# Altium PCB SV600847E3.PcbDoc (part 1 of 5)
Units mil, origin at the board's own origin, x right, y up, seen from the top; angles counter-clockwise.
Board outline 5404 x 2680 mil, 10 copper layers (Top Layer L1, Gnd-Plane - L2, Signals - L3, Gnd-Plane - L4, Pwr Plane - L5, Signals - L6, Gnd-Plane - L7, Signals - L8, Gnd-Plane - L9, Bottom Layer - L10), stack 57.8 mil thick; 517 components, 320 nets, 1784 pads, 1289 vias.
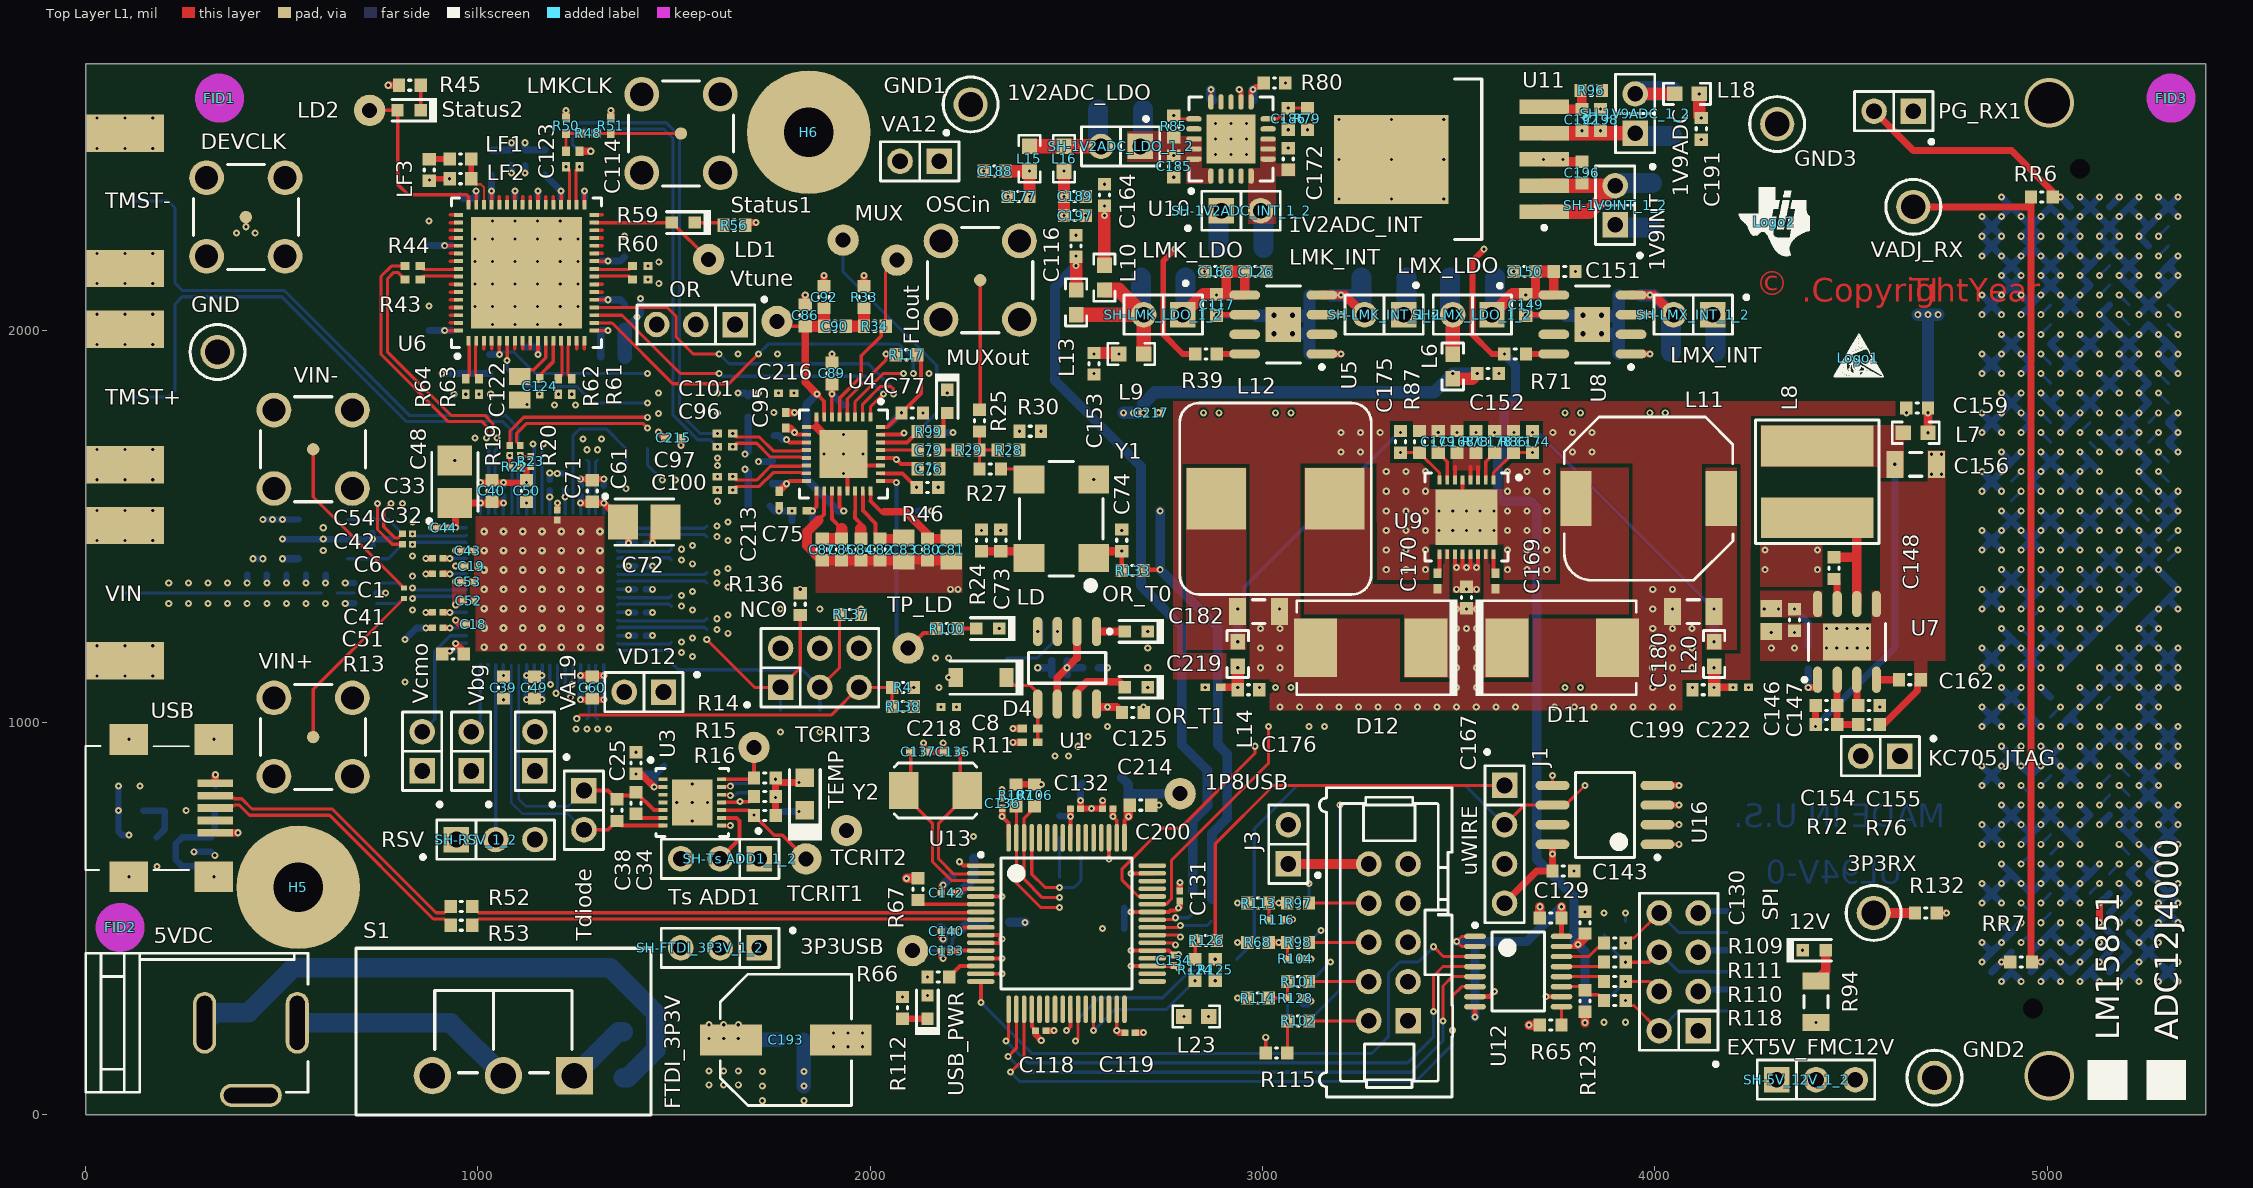
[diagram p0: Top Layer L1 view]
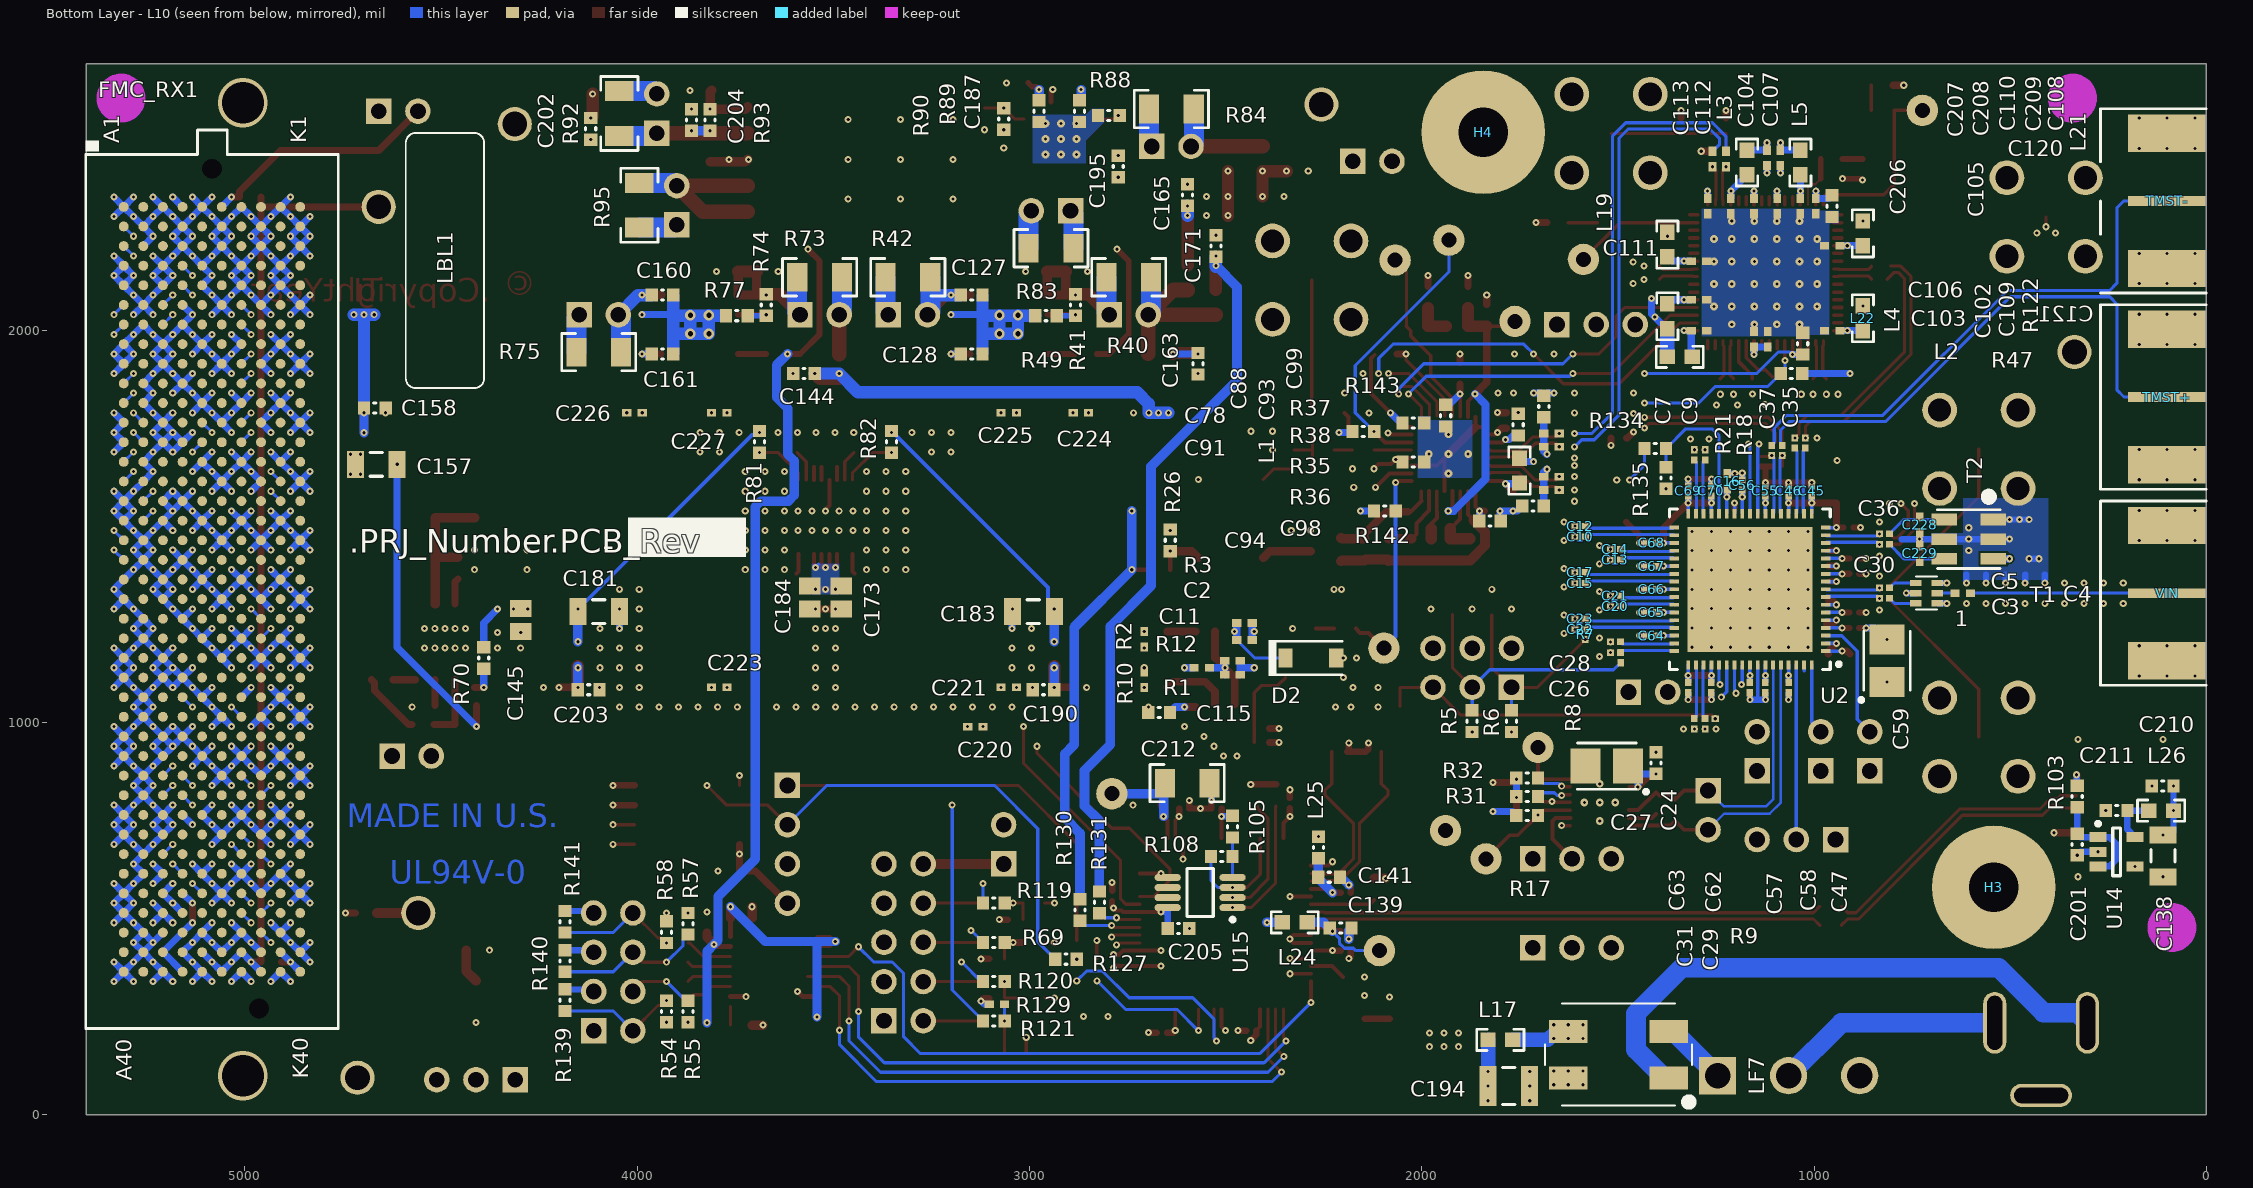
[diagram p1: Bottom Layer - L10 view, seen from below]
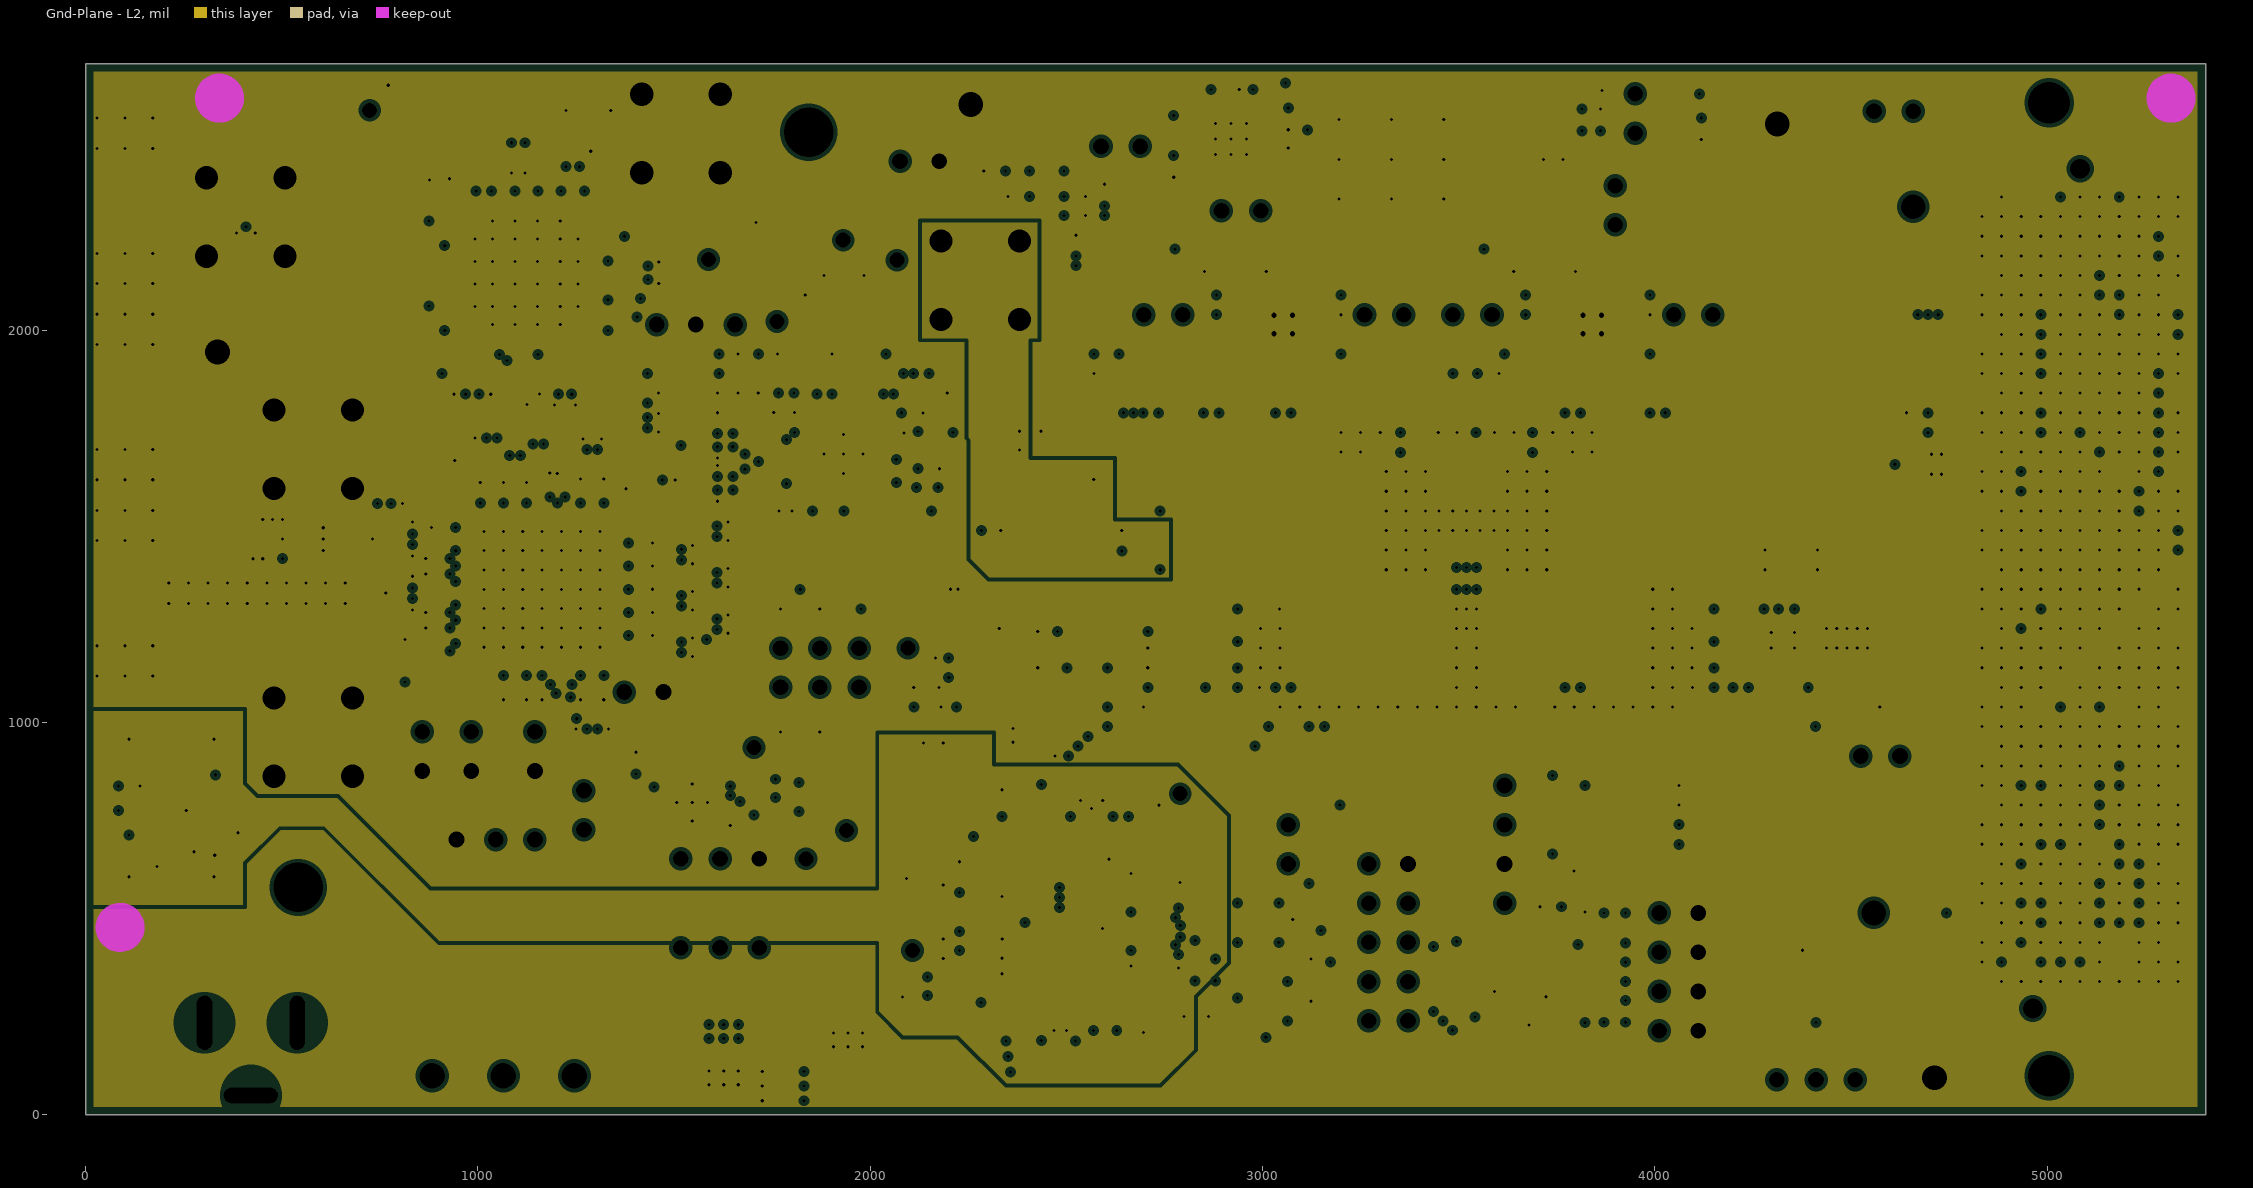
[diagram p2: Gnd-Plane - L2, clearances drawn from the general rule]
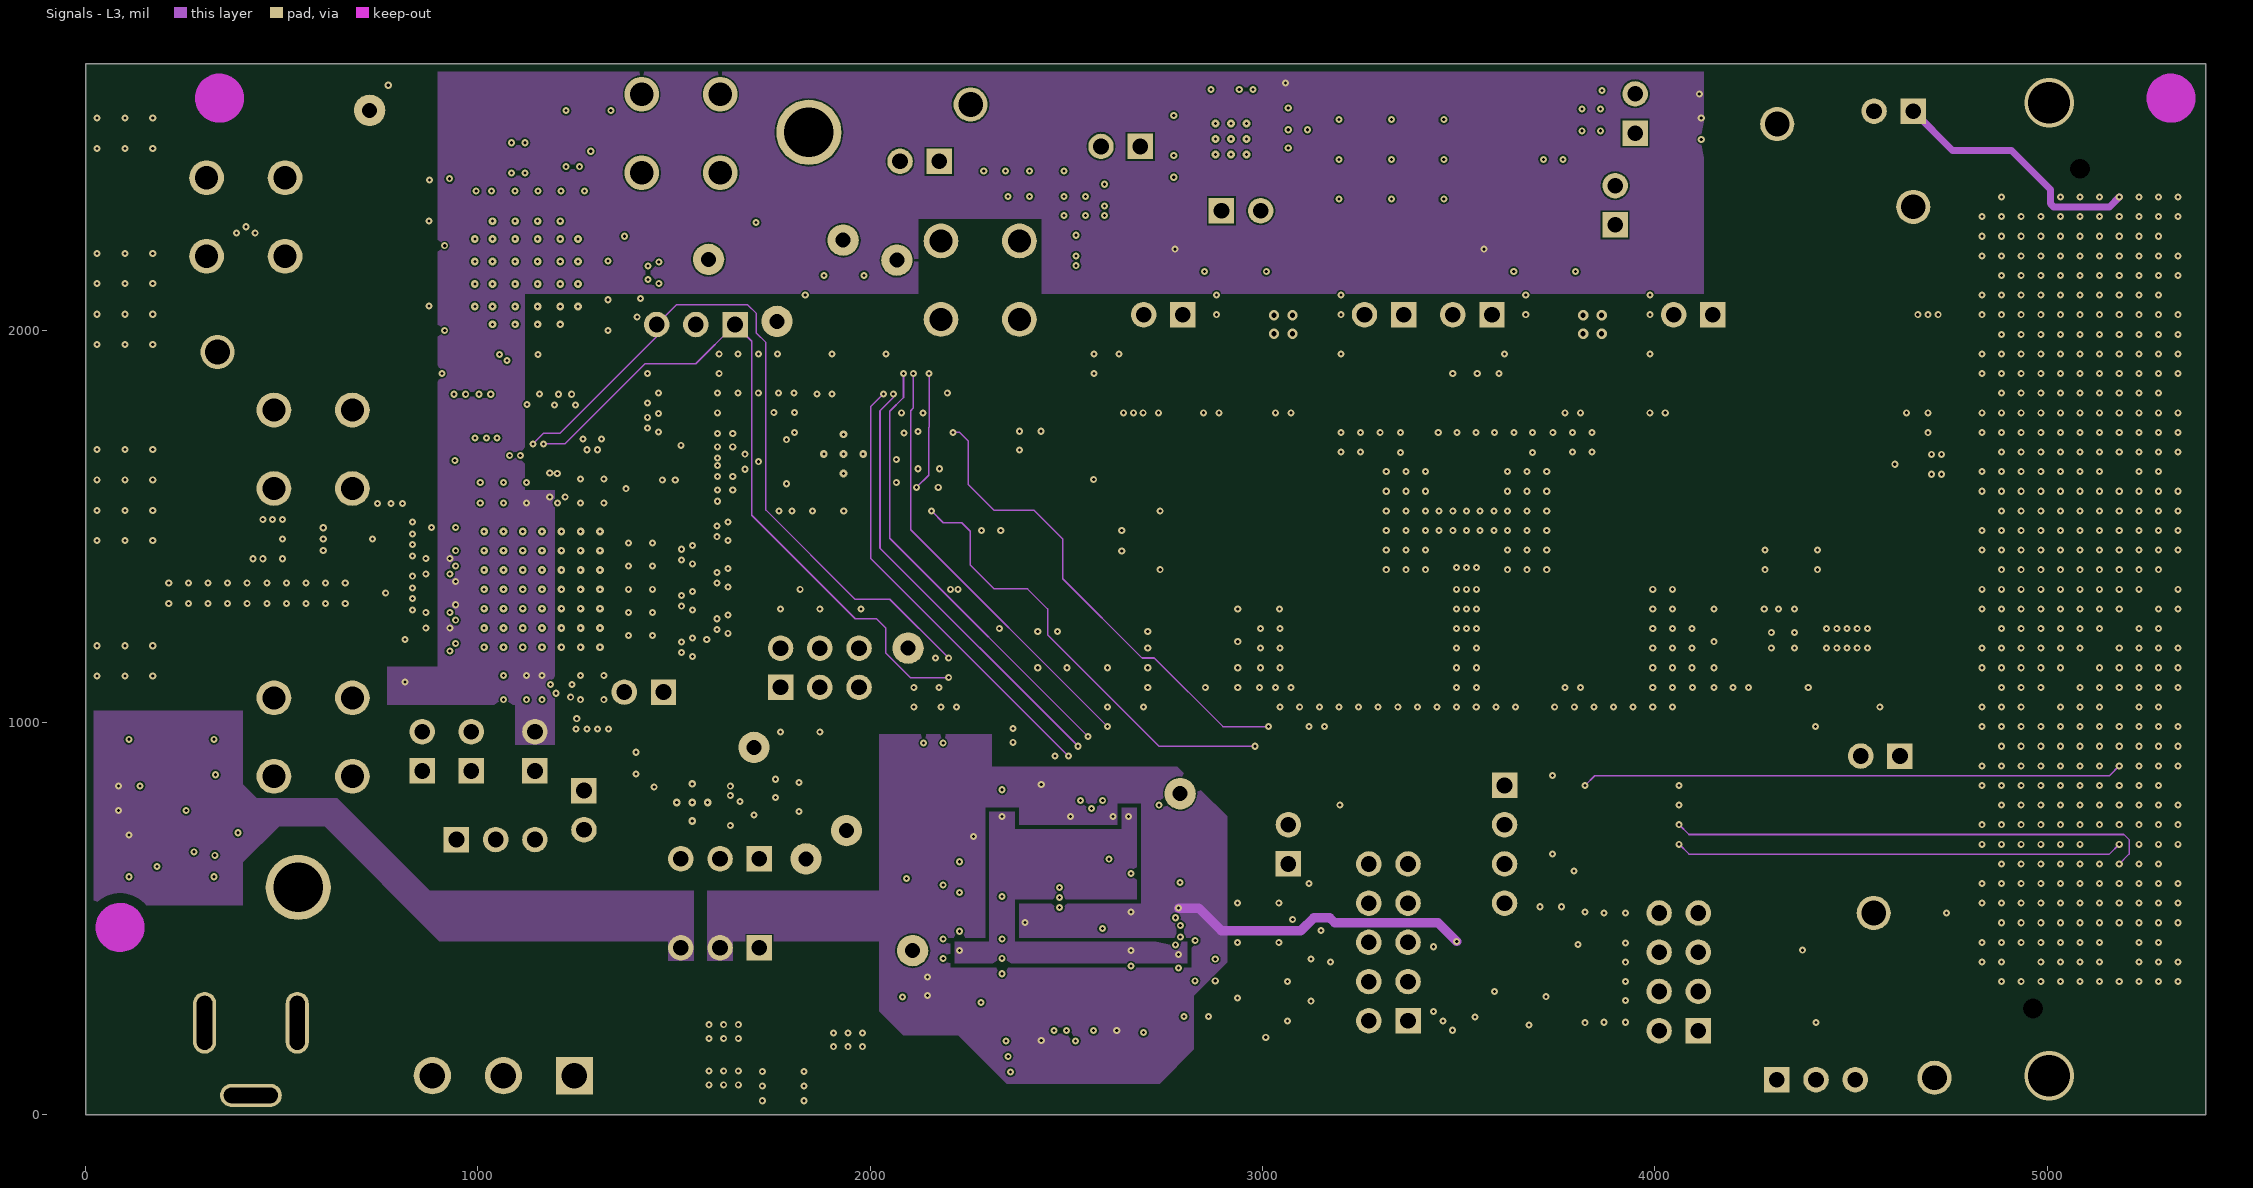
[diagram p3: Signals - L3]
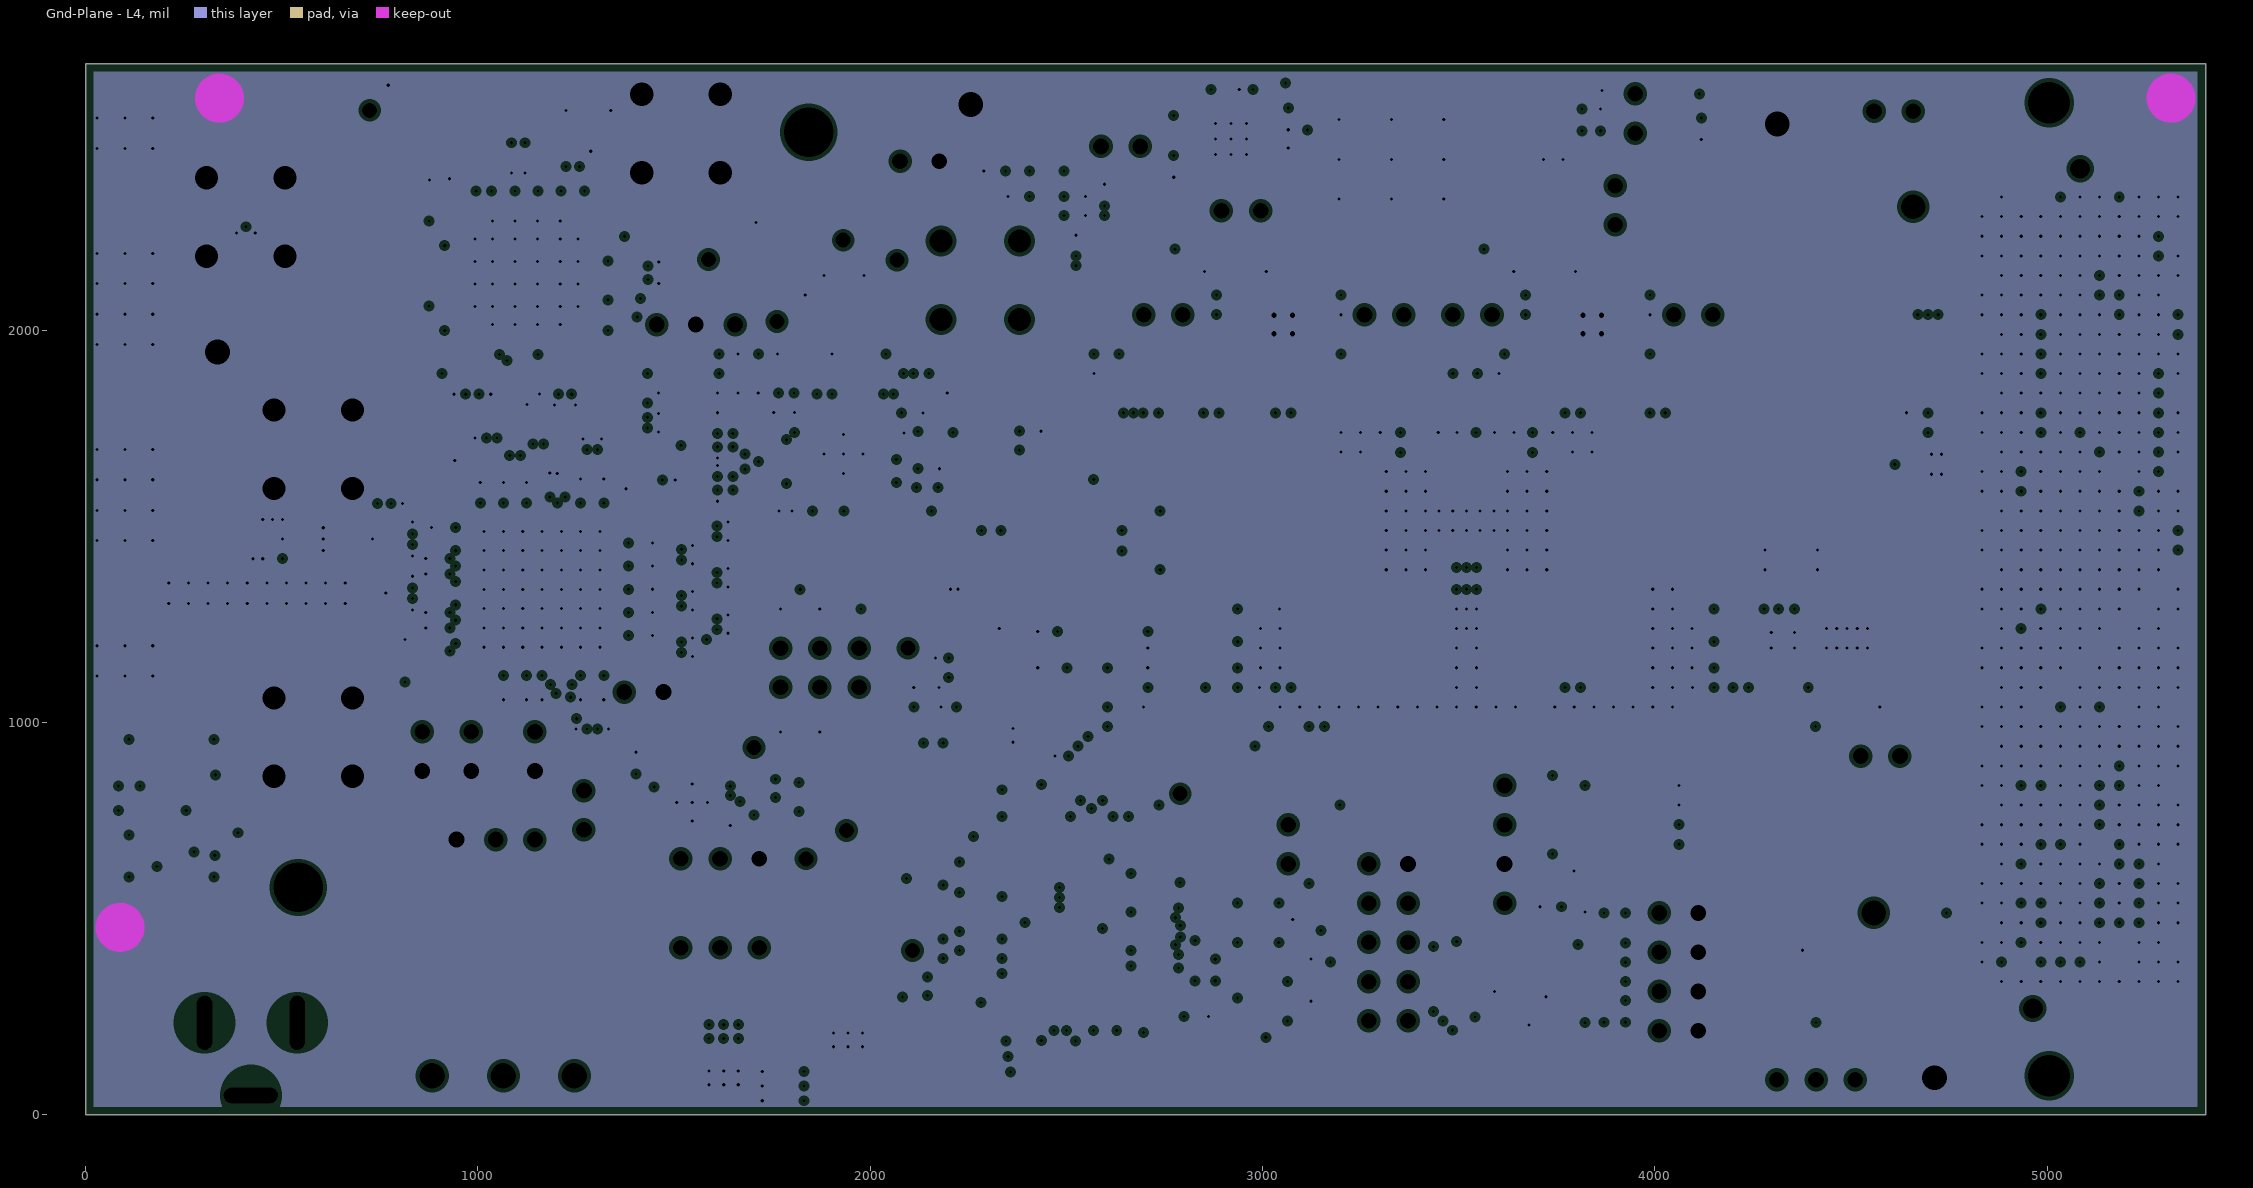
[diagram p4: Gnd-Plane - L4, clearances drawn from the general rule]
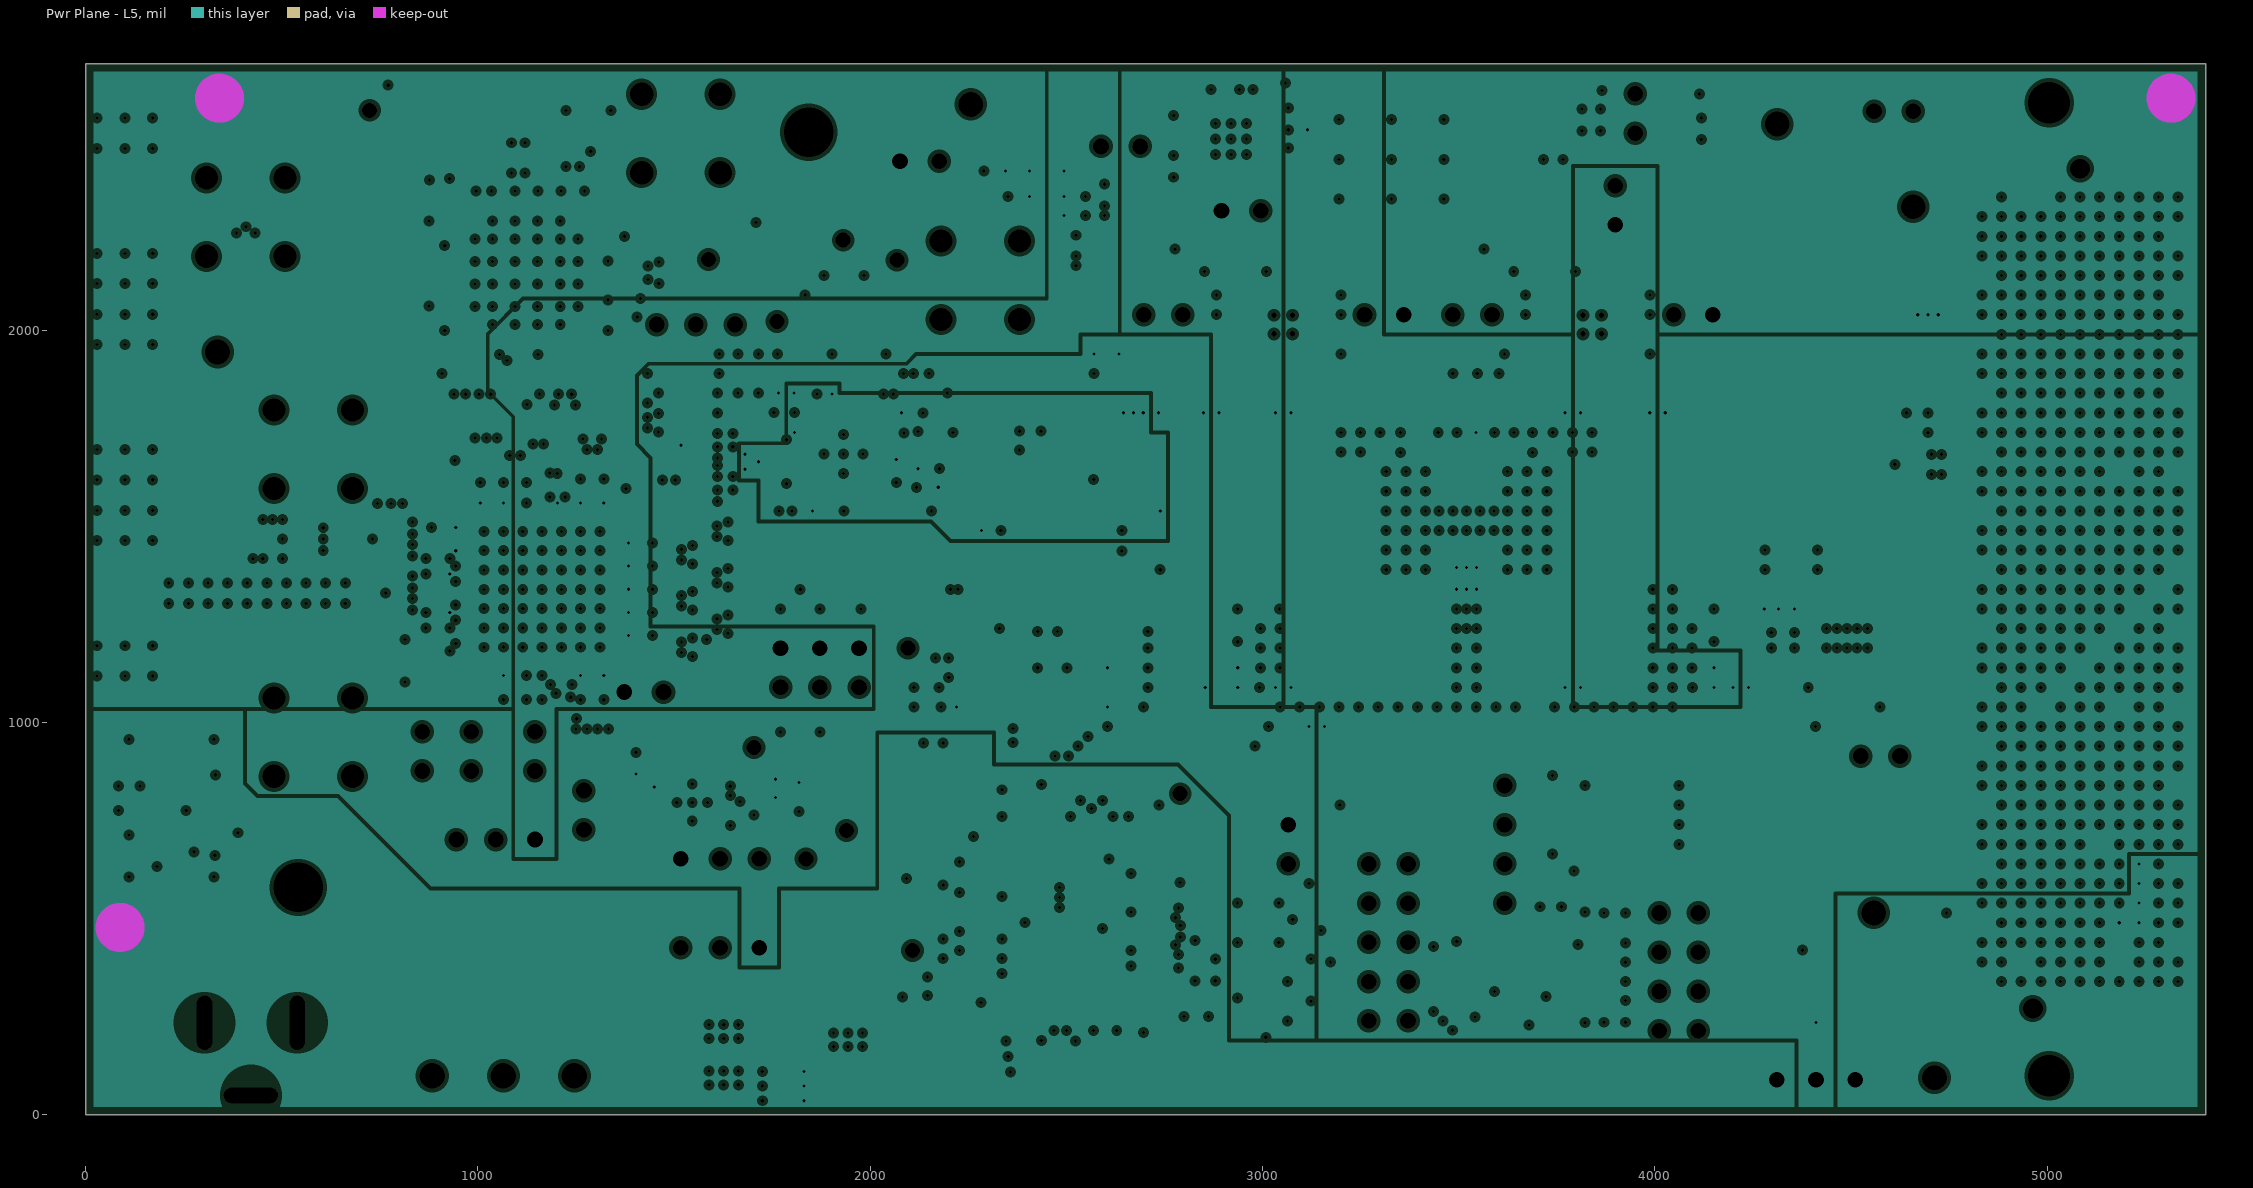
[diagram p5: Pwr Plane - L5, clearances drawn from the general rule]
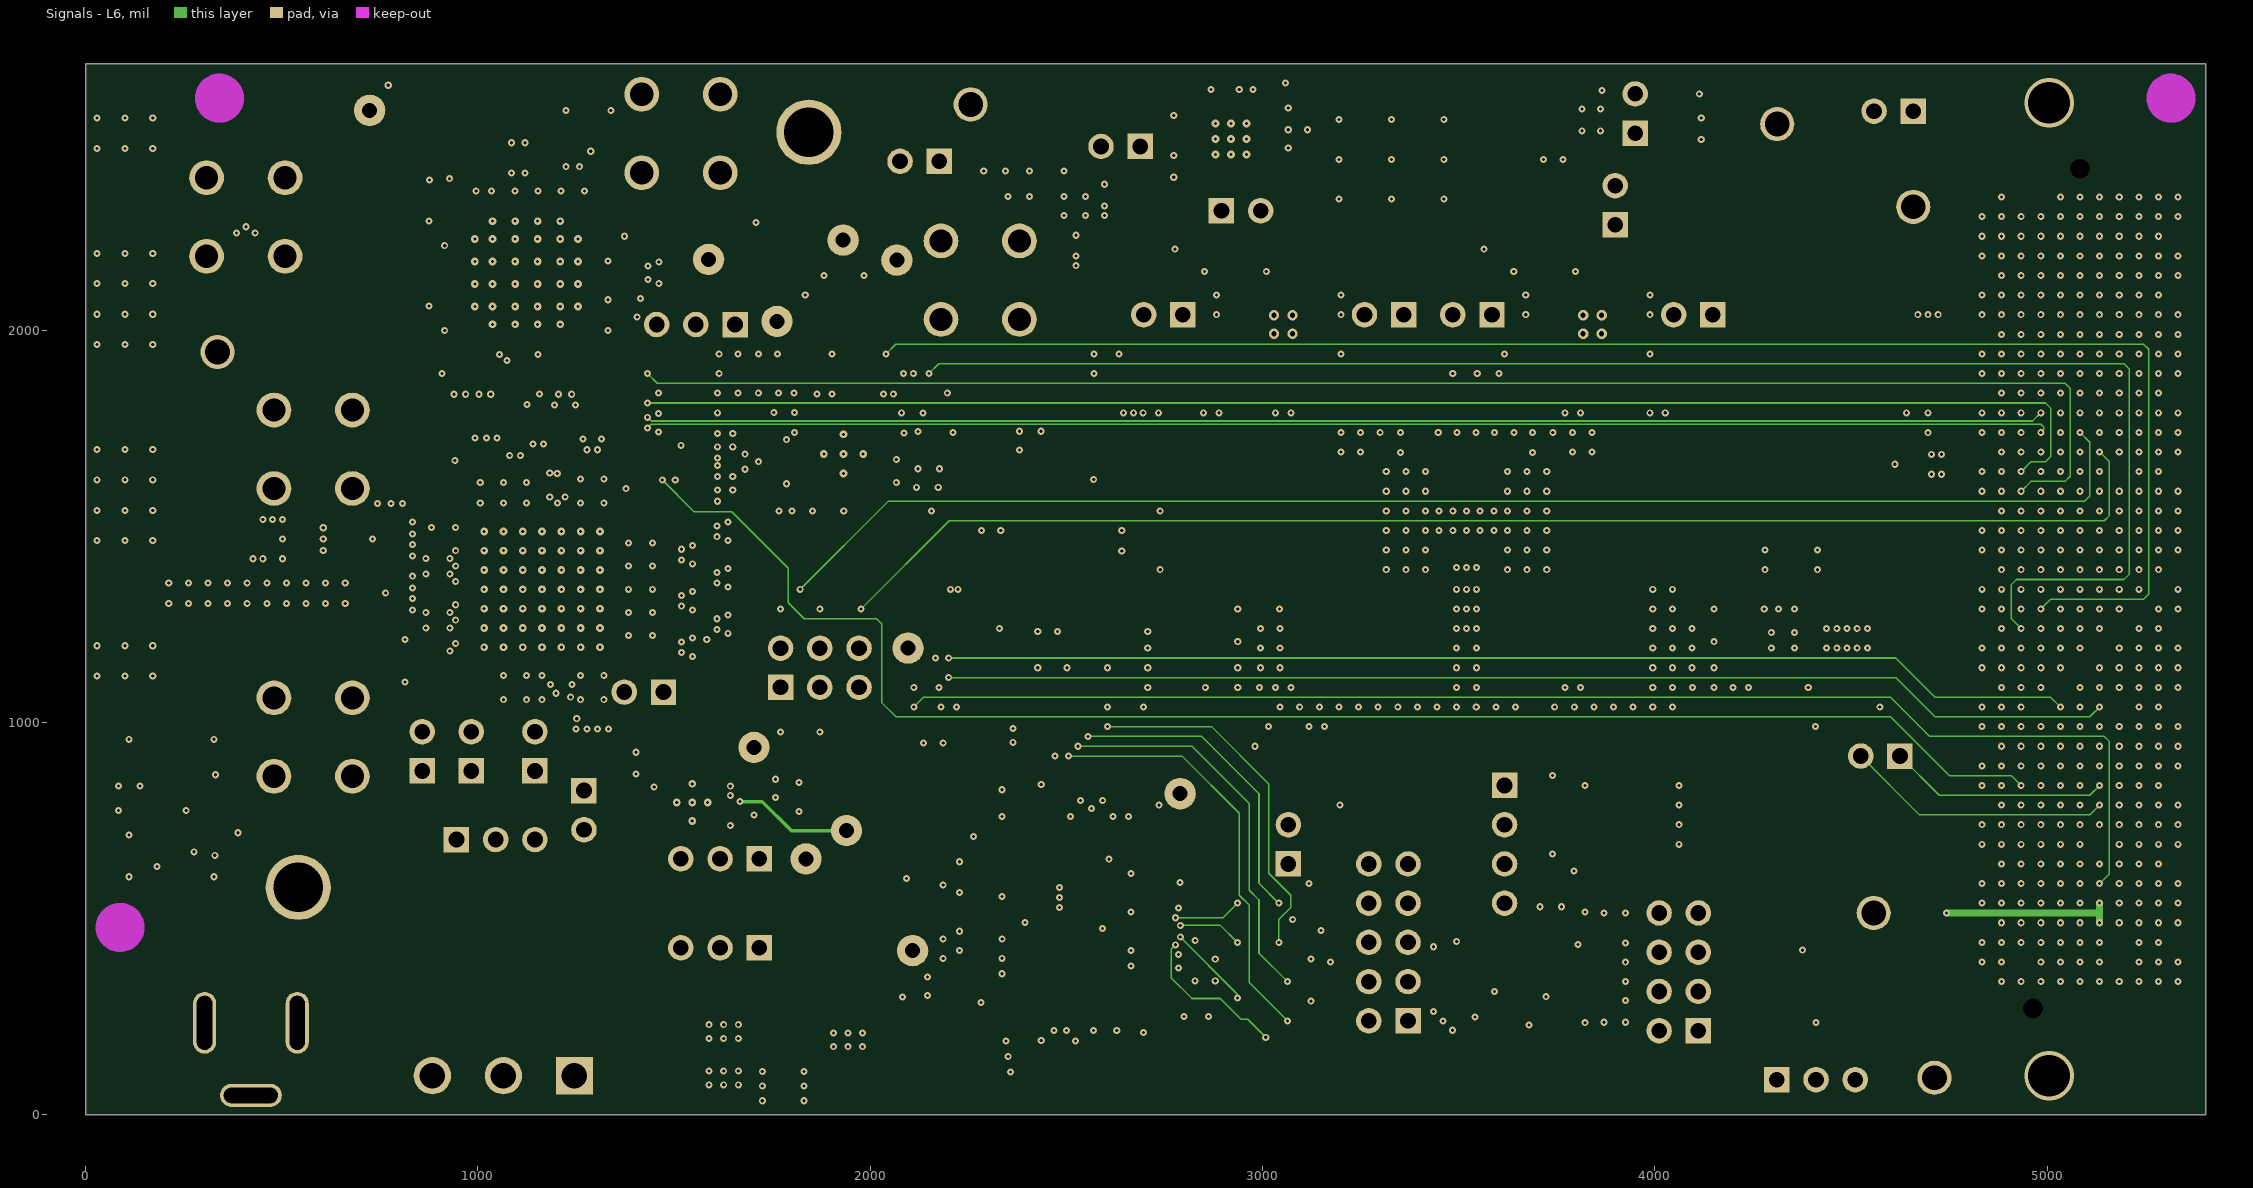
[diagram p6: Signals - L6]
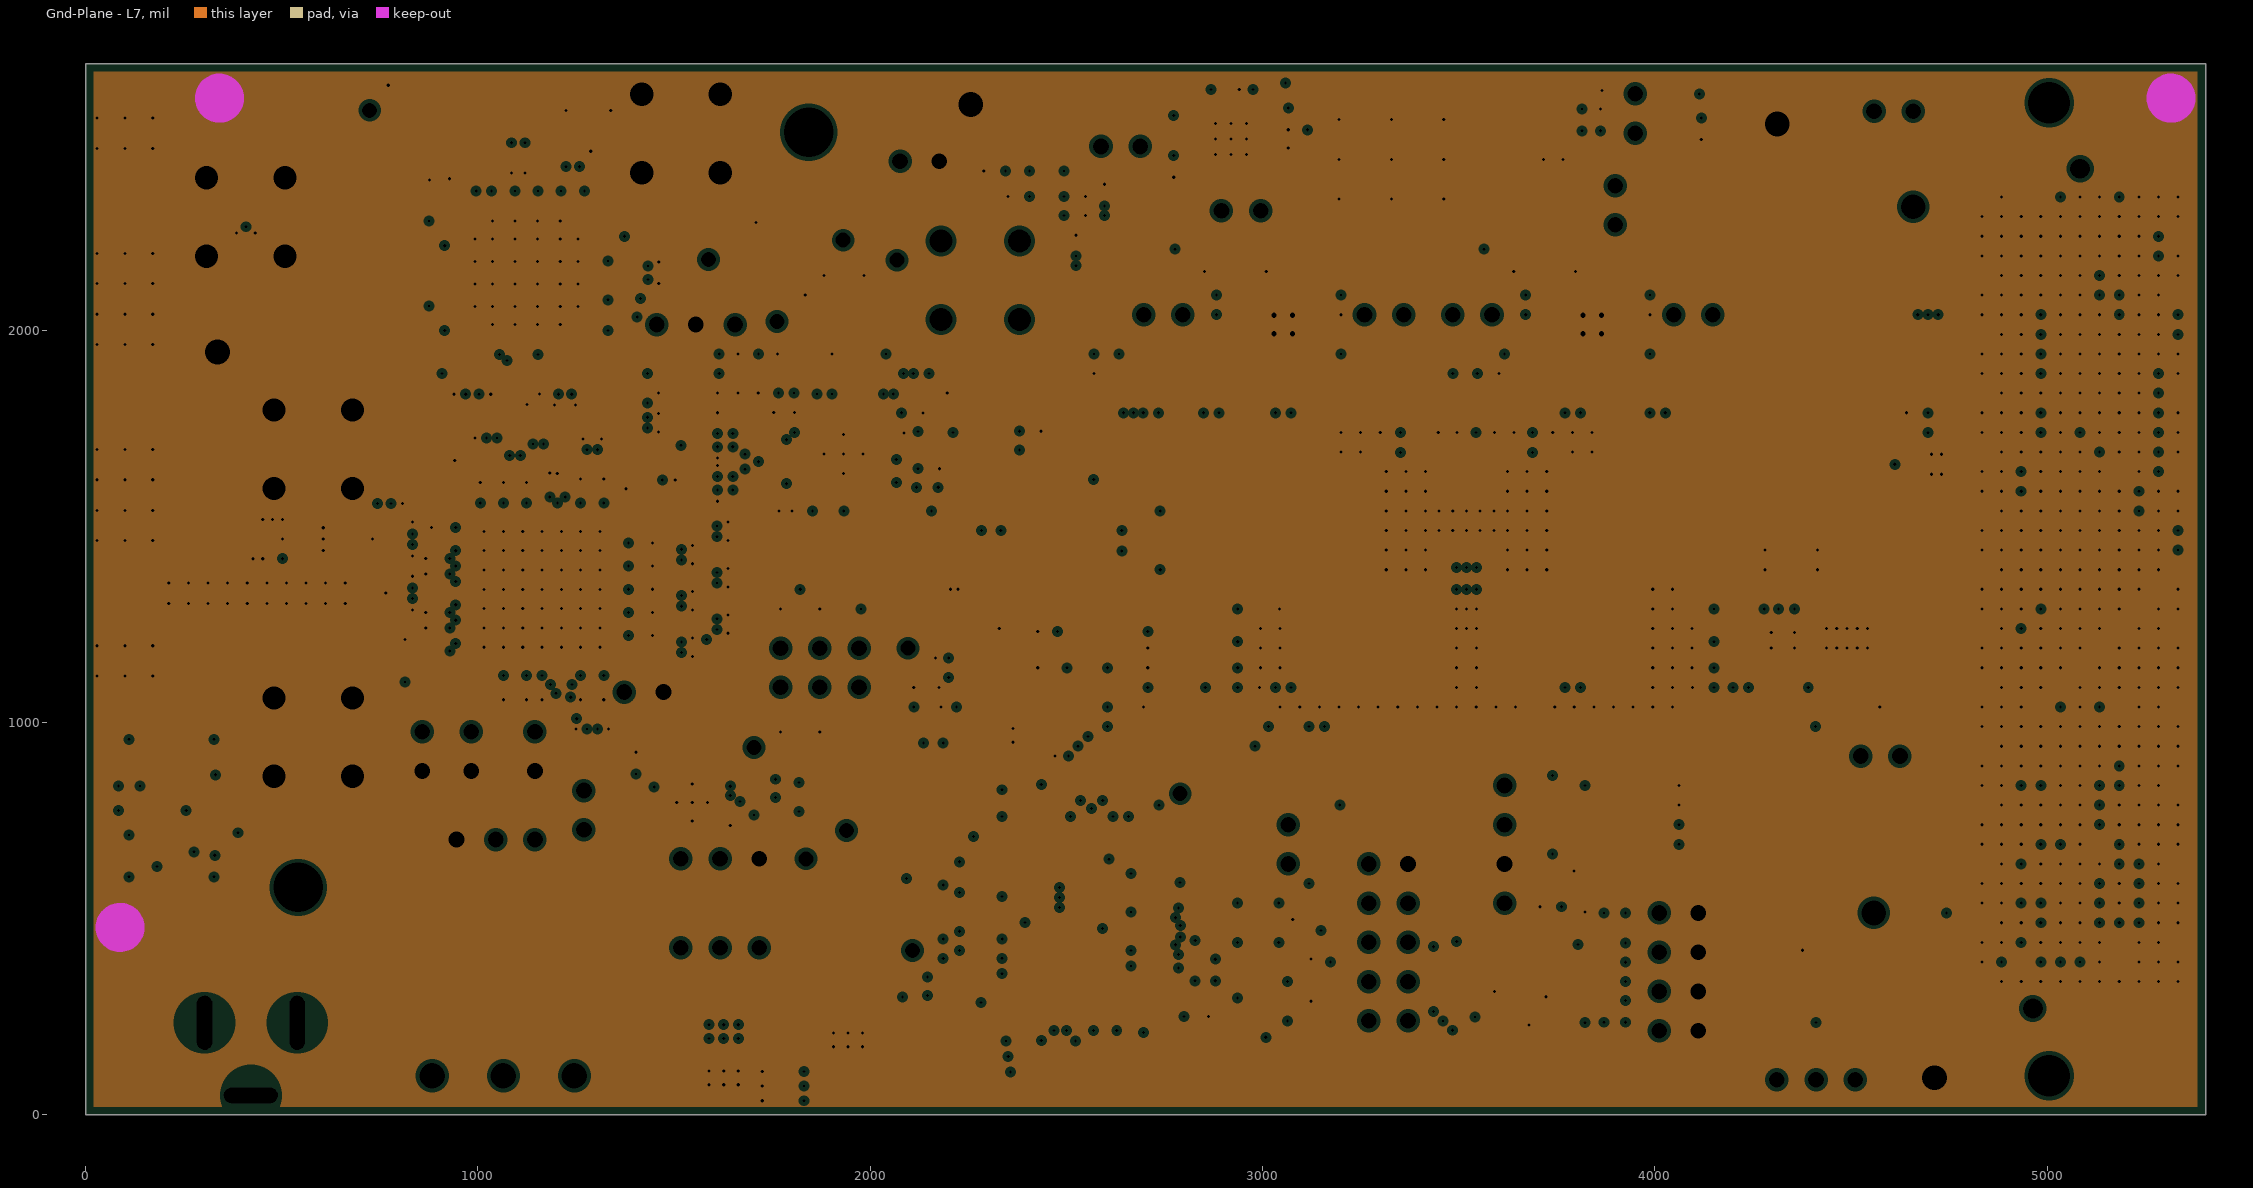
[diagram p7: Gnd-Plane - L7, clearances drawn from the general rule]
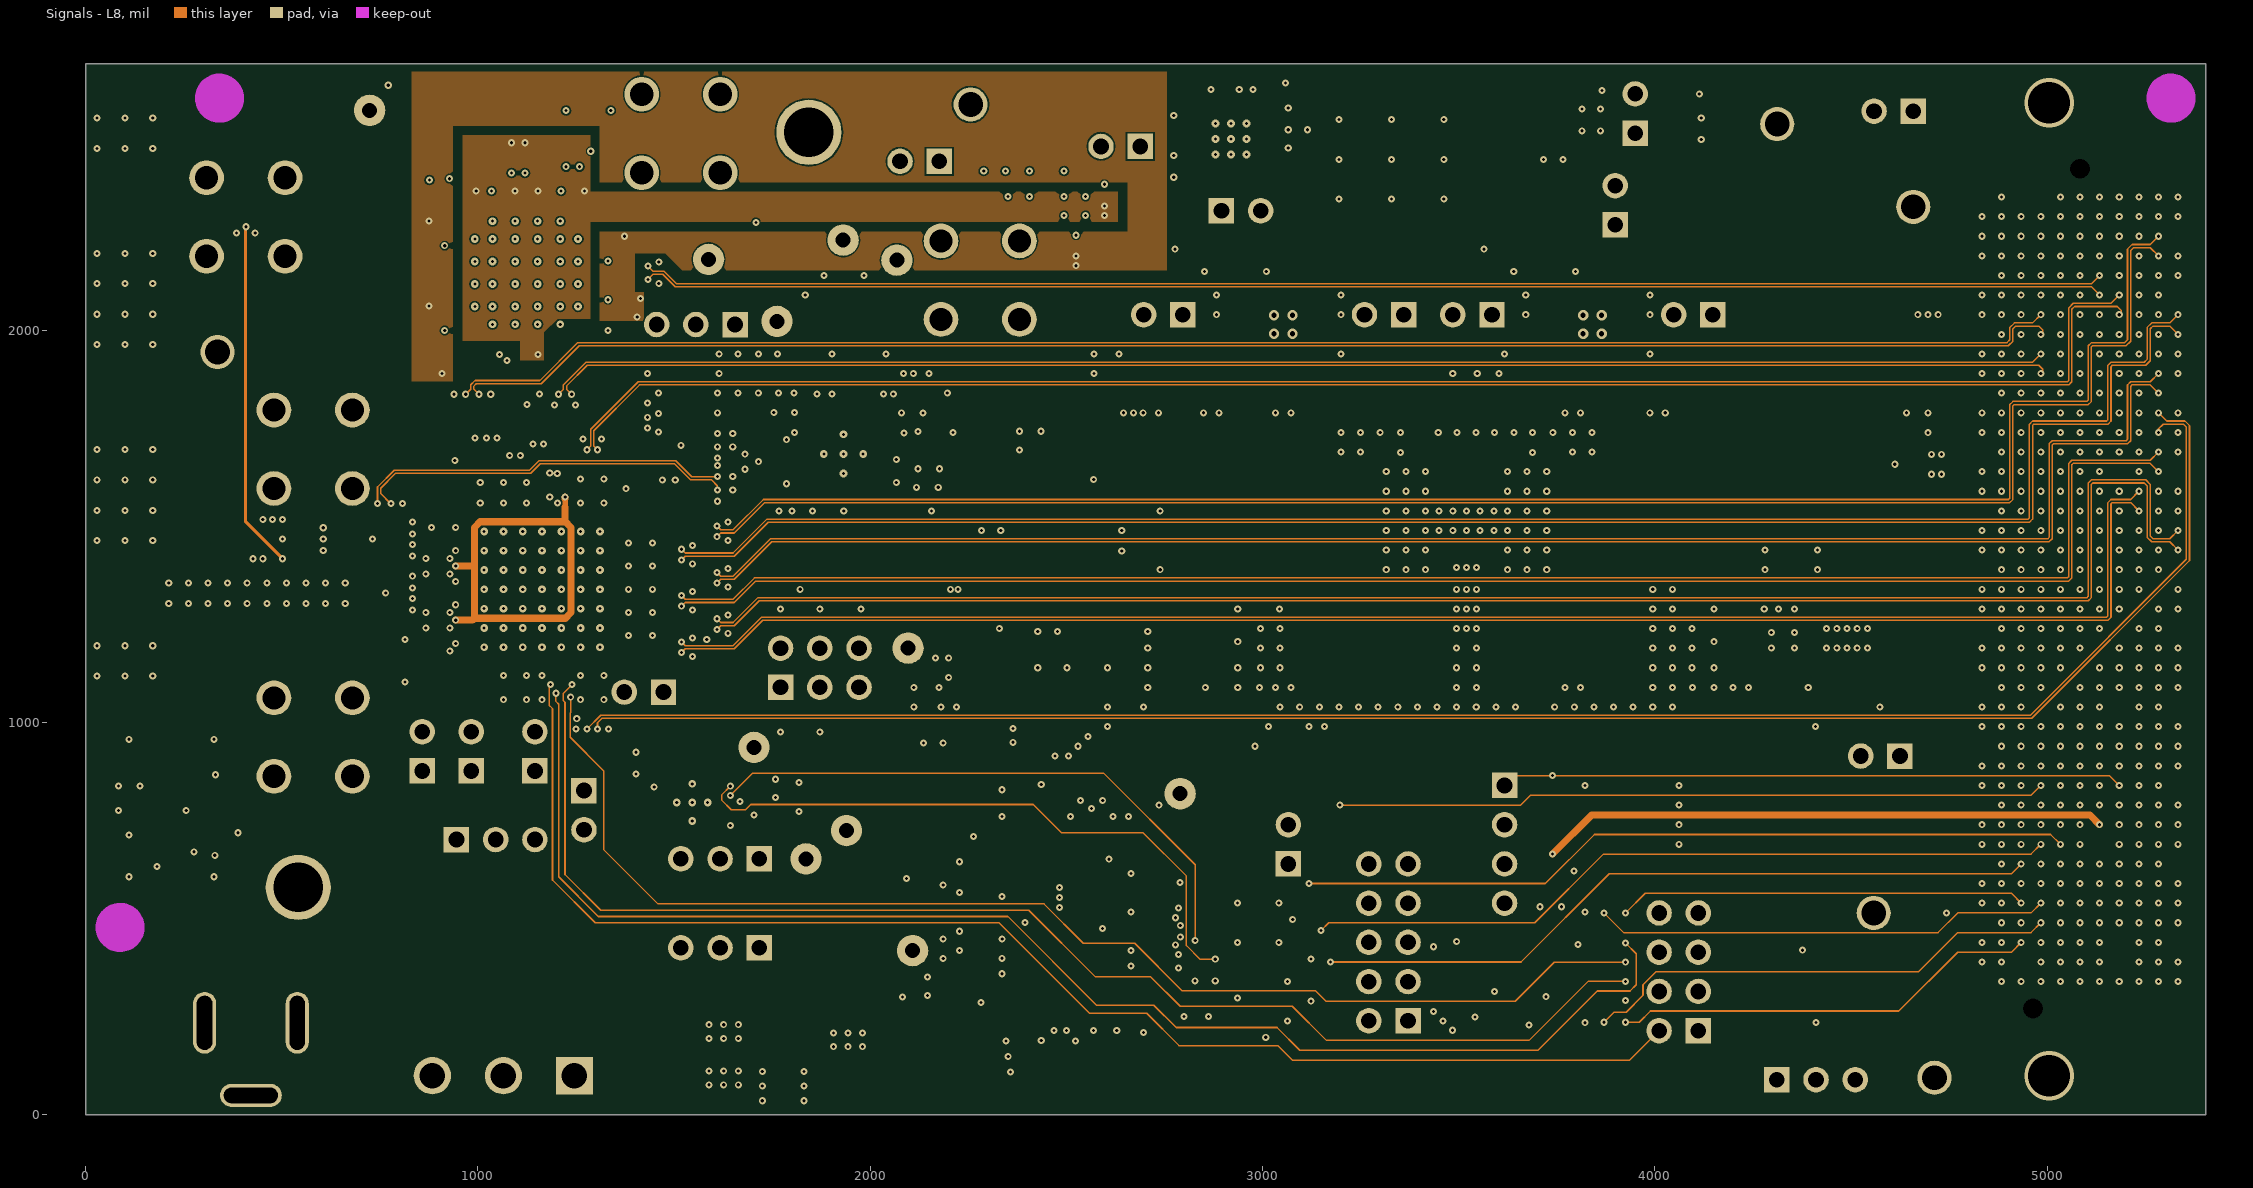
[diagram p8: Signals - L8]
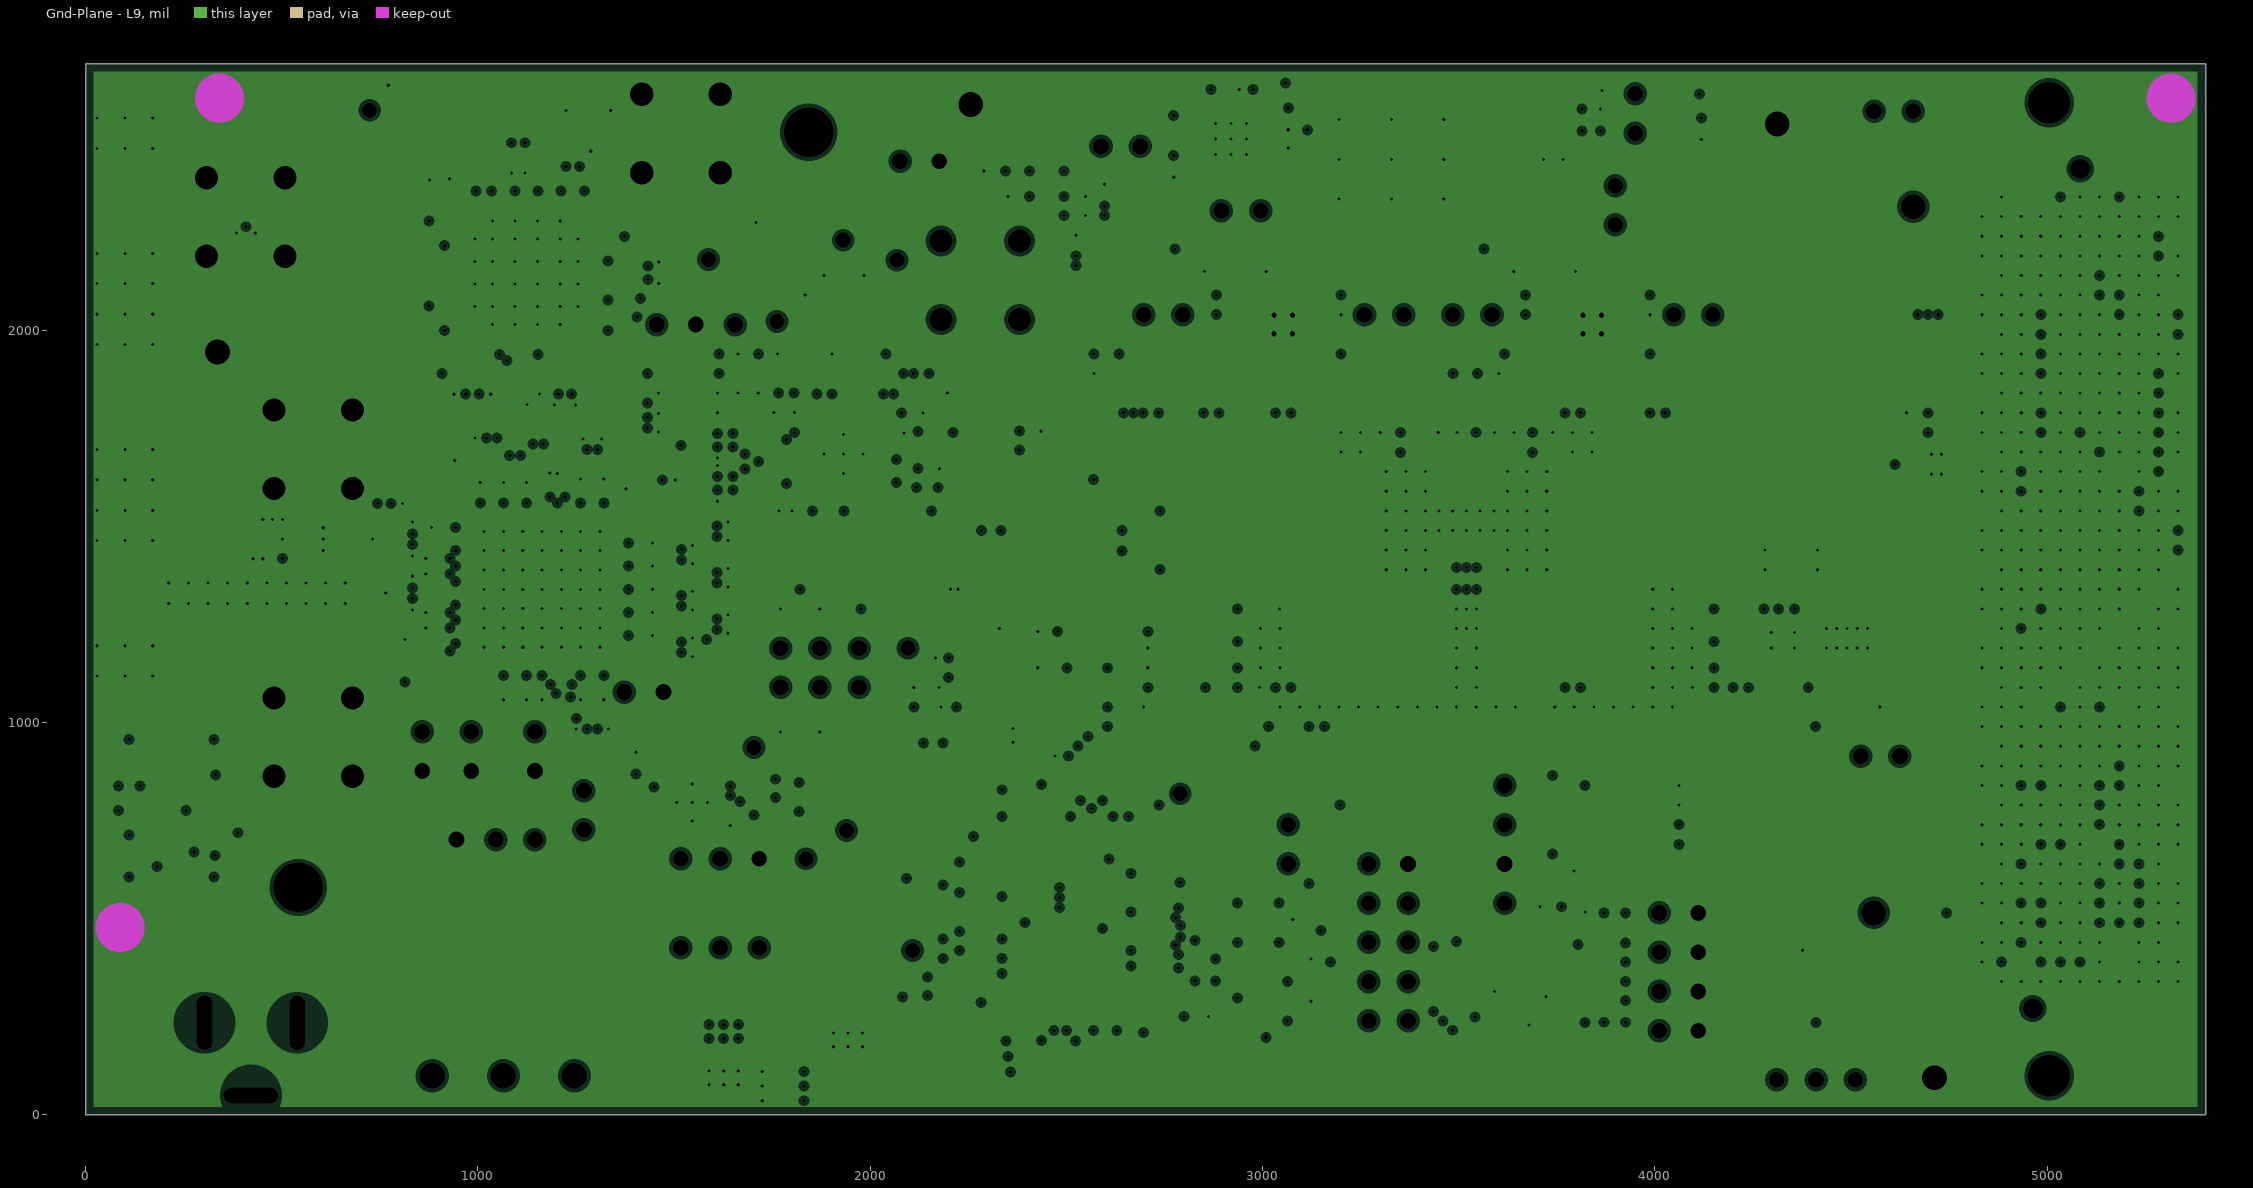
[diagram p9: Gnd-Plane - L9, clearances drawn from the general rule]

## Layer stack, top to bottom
Top Layer L1: signal copper 0.6
Dielectric: core 4, Rogers RO4350, Dk 3.66
Gnd-Plane - L2: plane copper 1.2, net (Multiple Nets)
Dielectric: prepreg 6.7, NP 4000-6, Dk 4.11
Signals - L3: signal copper 0.6
Dielectric: core 6, NP 4000-6, Dk 4.11
Gnd-Plane - L4: plane copper 1.2, net GND
Dielectric: prepreg 4.1, NP 4000-6, Dk 4.11
Pwr Plane - L5: plane copper 1.2, net (Multiple Nets)
Dielectric: core 6, NP 4000-6, Dk 4.11
Signals - L6: signal copper 0.6
Dielectric: prepreg 6.7, NP 4000-6, Dk 4.11
Gnd-Plane - L7: plane copper 1.2, net GND
Dielectric: core 4, Rogers RO4350, Dk 3.66
Signals - L8: signal copper 0.6
Dielectric: prepreg 7.3, Rogers RO4350, Dk 3.66
Gnd-Plane - L9: plane copper 1.2, net GND
Dielectric: core 4, Rogers RO4350, Dk 3.66
Bottom Layer - L10: signal copper 0.6

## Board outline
0,0 5404,0 5404,2680 0,2680

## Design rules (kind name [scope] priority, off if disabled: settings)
AcuteAngle [All] p1: minimum=4.50000000000000E+0001 checktracksonly=FALSE
AssemblyTestPointUsage [All] p1: valid=2
Clearance "0201 PADS" [HasFootprint('0201') vs HasFootprint('0201')] p1: gap=7.87
Clearance Clearance_BoardEdge_MountingHoles [OnCopper and InComponentClass('Mounting Holes') vs IsKeepOut] p2: gap=40
Clearance Clearance_BoardEdge_Poly [OnCopper and InPoly vs IsKeepOut] p3: gap=25
Clearance Clearance_BoardEdge [OnCopper and Not InComponentClass('Logo') and not InComponentClass('FiducialMark') and not InRegion(1000,500,4000,800) and Not IsKeepout vs IsKeepOut] p4: gap=25
Clearance [All] p5: gap=4
ComponentClearance ComponentClearance_Shared_Pad [(InComponent('R7') OR InComponent('R8') OR InComponent('R9') OR InComponent('C22') OR InComponent('C26') OR InComponent('C29') OR InComponent('SH-*') OR InComponent('RSV*') OR InComponent('Ts ADD1*') OR InComponent('LMX_INT*') OR InComponent('LMX_LDO*') OR InComponent('LMK_INT*') OR InComponent('LMK_LDO*') OR InComponent('1V2ADC_INT*') OR InComponent('1V2ADC_LDO*') OR InComponent('1V9INT*') OR InComponent('1V9ADC*') OR InComponent('+12V*'))] p1: gap=0 collisioncheckmode=3 verticalgap=0 showdistances=FALSE
ComponentClearance ComponentClearance_0201 [HasFootprint('0201*') or HasFootprint('LQA68A') vs HasFootprint('0201*') or HasFootprint('LQA68A')] p2: gap=10 collisioncheckmode=3 verticalgap=10 showdistances=FALSE
ComponentClearance ComponentClearance_ScrewToNut [(HasFootprint('NY PMS 440 0025 PH')) vs (HasFootprint('Keystone_1902C'))] p3: gap=5 collisioncheckmode=3 verticalgap=10 showdistances=FALSE
ComponentClearance ComponentClearance_MountingHoles [InComponentClass('Mounting Holes')] p4: gap=250 collisioncheckmode=3 verticalgap=100000 showdistances=FALSE
ComponentClearance ComponentClearance_SmallPassives [HasFootprint('0201*') or HasFootprint('0402*') or HasFootprint('0508') or HasFootprint('0603*') or HasFootprint('0612') or HasFootprint('0805*') or HasFootprint('0815*') or HasFootprint('0830*') or HasFootprint('1206*') or HasFootprint('1210*') or HasFootprint('1808*') or HasFootprint('1812*') or HasFootprint('1825*') or HasFootprint('2010*') or HasFootprint('2220*') or HasFootprint('2225*') or HasFootprint('2512*') or HasFootprint('2728*') or HasFootprint('3518*') or HasFootprint('LQA68A*')  or HasFootprint('RTV0032A*') or HasFootprint('DBV0005A*') or HasFootprint('XTAL_ABM3*') or HasFootprint('RGW0020A*') or HasFootprint('M08A*') or HasFootprint('LED_LTST-C190*') or HasFootprint('DDA0008B*') or HasFootprint('SOIJ-SM8*') or HasFootprint('MSOP-MS8*') or HasFootprint('SDA16A*') or HasFootprint('OSC_CWX*') or HasFootprint('3528-21*') or HasFootprint('PW0016A*') or HasFootprint('MRA08A*') or HasFootprint('TJ5A*') or HasFootprint('SOD-123*') or HasFootprint('RLY0068A*') vs HasFootprint('0201*') or HasFootprint('0402*') or HasFootprint('0508') or HasFootprint('0603*') or HasFootprint('0612') or HasFootprint('0805*') or HasFootprint('0815*') or HasFootprint('0830*') or HasFootprint('1206*') or HasFootprint('1210*') or HasFootprint('1808*') or HasFootprint('1812*') or HasFootprint('1825*') or HasFootprint('2010*') or HasFootprint('2220*') or HasFootprint('2225*') or HasFootprint('2512*') or HasFootprint('2728*') or HasFootprint('3518*') or HasFootprint('LQA68A*')  or HasFootprint('RTV0032A*') or HasFootprint('DBV0005A*') or HasFootprint('XTAL_ABM3*') or HasFootprint('RGW0020A*') or HasFootprint('M08A*') or HasFootprint('LED_LTST-C190*') or HasFootprint('DDA0008B*') or HasFootprint('SOIJ-SM8*') or HasFootprint('MSOP-MS8*') or HasFootprint('SDA16A*') or HasFootprint('OSC_CWX*') or HasFootprint('3528-21*') or HasFootprint('PW0016A*') or HasFootprint('MRA08A*') or HasFootprint('TJ5A*') or HasFootprint('SOD-123*') or HasFootprint('RLY0068A*')] p5: gap=10 collisioncheckmode=3 verticalgap=10 showdistances=FALSE
ComponentClearance ComponentClearance_THtoSMT [IsThruComponent vs IsSMTComponent] p6: gap=10 collisioncheckmode=3 verticalgap=0 showdistances=FALSE
ComponentClearance ComponentClearance_THtoTH [IsThruComponent vs IsThruComponent] p7: gap=10 collisioncheckmode=3 verticalgap=100000 showdistances=FALSE
ComponentClearance [All] p8: gap=10 collisioncheckmode=3 verticalgap=10 showdistances=FALSE
DiffPairsRouting [All] p1: maxlimit=100 minlimit=4 mostfreqgap=4 toplayer_mingap=8 toplayer_prefgap=8 bottomlayer_mingap=8 bottomlayer_prefgap=8 maxuncoupledlength=1000
FabricationTestPointUsage TestPointUsage [All] p1: valid=2 allowmultiple=FALSE
FabricationTestpoint Testpoint [All] p1: side=3 testpointundercomponent=TRUE minsize=40 maxsize=100 preferedsize=60 minholesize=0 maxholesize=40 preferedholesize=32 testpointgrid=1 allowsidetop=TRUE allowsidebottom=TRUE usegrid=TRUE gridtolerance=0.01
FanoutControl Fanout_LCC [IsLCC] p1: bgadir=Out bgaviamode=Centered fanoutstyle=Auto fanoutdirection=Alternating viagrid=1 // Fanout_LCC (Default Rule)
FanoutControl Fanout_BGA [IsBGA] p2: bgadir=Out bgaviamode=Centered fanoutstyle=Auto fanoutdirection=Alternating viagrid=1 // Fanout_BGA (Default Rule)
FanoutControl Fanout_Default [All] p4: bgadir=Out bgaviamode=Centered fanoutstyle=Auto fanoutdirection=Alternating viagrid=1 // Fanout_Default (Default Rule)
FanoutControl Fanout_Small [(CompPinCount < 5)] p5: bgadir=Out bgaviamode=Centered fanoutstyle=Auto fanoutdirection=OutThenIn viagrid=1 // Fanout_Small (Default Rule)
HoleSize [All] p1: absolutevalues=TRUE maxlimit=251 minlimit=7.87 maxpercent=80.000 minpercent=20.000
MinimumAnnularRing [All] p1: minimumring=5
MinimumSolderMaskSliver MinimumSolderMaskSliver_Logo [InComponentClass('Logo') vs InComponentClass('Logo')] p1: minsoldermaskwidth=0.7
MinimumSolderMaskSliver [All] p2: minsoldermaskwidth=4
NetAntennae "NetAntennae U2 or U6" [(InNet('U2-*') OR InNet('U6-*'))] p1: netantennaetolerance=50
NetAntennae [All] p2: netantennaetolerance=0
PlaneClearance [All] p1: clearance=10
PlaneConnect [All] p1: planeconnectstyle=Direct reliefexpansion=10 reliefentries=4 reliefconductorwidth=10 reliefairgap=10
PolygonConnect [All] p1: connectstyle=Direct reliefconductorwidth=10 reliefentries=4 polygonreliefangle="90 Angle" airgapwidth=10
RoutingVias [All] p1: holewidth=16 width=34 viastyle="Through Hole" minholewidth=7.87 minwidth=18 maxholewidth=106 maxwidth=126
SMDToCorner [All] p1: distance=30000
SilkToSilkClearance [All] p1: silktosilkclearance=5
SilkscreenOverComponentPads [All] p1: minsilkscreentomaskgap=5
SolderMaskExpansion [All] p1: expansion=3
Width [All] p1: maxlimit=100 minlimit=4 preferedwidth=10 checkconnectedcopper=TRUE
12 further rules are at their usual default settings.

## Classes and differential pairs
differential pair RFOUTB: +RFOUTB_P -RFOUTB_N
differential pair RFOUTA: +RFOUTA_P -RFOUTA_N
differential pair LMX_OUTB: +LMX_OUTB_P -LMX_OUTB_N
differential pair LMX_OUTA: +LMX_OUTA_P -LMX_OUTA_N
differential pair SYNC~/TMST: +SYNC~/TMST_P -SYNC~/TMST_N
differential pair VIN: +VIN_P -VIN_N
differential pair SYSRF: +SYSRF_P -SYSRF_N
differential pair SYSREFTX: +SYSREFTX_P -SYSREFTX_N
differential pair SYSREFRX: +SYSREFRX_P -SYSREFRX_N
differential pair SYNC: +SYNC_P -SYNC_N
differential pair DEVCLK: +DEVCLK_P -DEVCLK_N
differential pair DEVCLKBRX: +DEVCLKBRX_P -DEVCLKBRX_N
differential pair DEVCLKARX: +DEVCLKARX_P -DEVCLKARX_N
differential pair D7: +D7_P -D7_N
differential pair D6: +D6_P -D6_N
differential pair D5: +D5_P -D5_N
differential pair D4: +D4_P -D4_N
differential pair D3: +D3_P -D3_N
differential pair D2: +D2_P -D2_N
differential pair D1: +D1_P -D1_N
differential pair D0: +D0_P -D0_N
differential pair CLKIN1: +CLKIN1_P -CLKIN1_N
differential pair CLK4: +CLK4_P -CLK4_N
differential pair CLK0: +CLK0_P -CLK0_N
differential pair CLK11: +CLK11_P -CLK11_N
differential pair CLK3: +CLK3_P -CLK3_N
differential pair TMST: +TMST_P -TMST_N

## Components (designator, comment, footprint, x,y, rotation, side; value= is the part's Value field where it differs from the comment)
1P8USB "TESTPOINT" TESTPOINT 2790,819 r90 top
1V2ADC_INT "TSW-102-07-G-S" TSW-102-07-G-S 2945.26,2305 r0 top
1V2ADC_LDO "TSW-102-07-G-S" TSW-102-07-G-S 2638.27,2469 r180 top
1V9ADC "TSW-102-07-G-S" TSW-102-07-G-S 3950,2552.93 r90 top
1V9INT "TSW-102-07-G-S" TSW-102-07-G-S 3899,2319.07 r90 top
3P3RX "5011" Keystone5011 4558,515 r90 top
3P3USB "TESTPOINT" TESTPOINT 2108,419 r90 top
5VDC "PJ-202AH" CONN_CUI-PJ-202AH 539.37,235 r180 top
12V "LTST-C190GKT" LED_LTST-C190 4406.47,420 r180 top
C1 "GRM033R71C101KA01D" 0201L 822.55,1316.66 r180 top
C2 "GRM155R71A104KA01D" 0402L 2452,1210.67 r180 bottom
C3 "GRM033R71C101KA01D" 0201 820.58,1316.66 r180 bottom
C4 "GRM1555C1H100JA01D" 0402L 621,1330.16 r180 bottom
C5 "GRM033R71C101KA01D" 0201 820.58,1343.66 r180 bottom
C6 "GRM033R71C101KA01D" 0201L 822.55,1343.66 r0 top
C7 "C0603X5R0J104K" 0201 1304.84,1682.81 r270 bottom
C8 "GRM155R71A104KA01D" 0402L 2407.32,985 r180 top
C9 "C0603X5R0J104K" 0201 1277.84,1682.81 r270 bottom
C10 "C0603X5R0J104K" 0201 1596.19,1474.14 r180 bottom
C11 "GRM155R71A104KA01D" 0402L 2482.32,1158 r180 bottom
C12 "C0603X5R0J104K" 0201 1596.19,1501.14 r180 bottom
C13 "C0603X5R0J104K" 0201 1506.19,1415.08 r180 bottom
C14 "C0603X5R0J104K" 0201 1506.19,1442.08 r180 bottom
C15 "C0603X5R0J104K" 0201 1596.19,1356.03 r180 bottom
C16 "C1005X5R0J475M050BC" 0402L 1221,1615.62 r270 bottom
C17 "C0603X5R0J104K" 0201 1596.19,1383.03 r180 bottom
C18 "C1005X5R1A104K" 0402L 988.26,1251.2 r180 top
C19 "C1005X5R1A104K" 0402L 983.2,1399.05 r180 top
C20 "C0603X5R0J104K" 0201 1506.19,1296.97 r180 bottom
C21 "C0603X5R0J104K" 0201 1506.19,1323.97 r180 bottom
C22 "C0603X5R0J104K" 0201 1596.19,1237.92 r180 bottom
C23 "C0603X5R0J104K" 0201 1596.19,1264.92 r180 bottom
C24 "0603YC104JAT2A" 0603L 1403.28,897.03 r90 bottom
C25 "06035A101JAT2A" 0603L 1403.28,897.03 r90 top
C26 "C0603X5R0J104K" 0201 1506.19,1178.86 r180 bottom
C27 "293D106X0010B2TE3" 3528-21 1528.28,889.42 r0 bottom
C28 "C0603X5R0J104K" 0201 1506.19,1205.86 r180 bottom
C29 "C0603X5R0J104K" 0201 1277.84,997.19 r90 bottom
C30 "C0603X5R0J224M" 0201 820.58,1454.45 r180 bottom
C31 "C0603X5R0J104K" 0201 1304.84,997.19 r90 bottom
C32 "GRM033R61A472KA01D" 0201 820.58,1454.45 r180 top
C33 "GRM033R61A472KA01D" 0201 820.58,1481.45 r180 top
C34 "06035A101JAT2A" 0603L 1403.28,795 r90 top
C35 "GRM033R61A472KA01D" 0201 1021.93,1713 r90 bottom
C36 "C0603X5R0J224M" 0201 820.58,1481.45 r180 bottom
C37 "GRM033R61A472KA01D" 0201 1048.93,1713 r90 bottom
C38 "06035A101JAT2A" 0603L 1354.28,777 r90 top
C39 "C1608X5R1A105K" 0603L 1064.96,1089.26 r270 top
C40 "C1608X5R1A105K" 0603L 1035.43,1590.74 r90 top
C41 "C0603X5R0J104K" 0201 897.65,1280.94 r0 top
C42 "C0603X5R0J104K" 0201 897.65,1379.37 r0 top
C43 "C0603X5R0J104K" 0201 973.87,1438.43 r180 top
C44 "C0603X5R0J104K" 0201 912.65,1497.48 r0 top
C45 "C0603X5R0J104K" 0201 1005.91,1590.74 r270 bottom
C46 "C0603X5R0J104K" 0201 1064.96,1590.74 r270 bottom
C47 "C0603X5R0J104K" 0201 1064.96,1089.26 r90 bottom
C48 "293D106X0010B2TE3" 3528-21 941,1614 r90 top
C49 "C1608X5R1A105K" 0603L 1143.7,1089.26 r270 top
C50 "C1608X5R1A105K" 0603L 1124.02,1590.74 r90 top
C51 "C0603X5R0J104K" 0201 897.65,1241.57 r0 top
C52 "C0603X5R0J104K" 0201 976.57,1310.95 r180 top
C53 "C0603X5R0J104K" 0201 973.87,1359.68 r180 top
C54 "C0603X5R0J104K" 0201 897.65,1418.74 r0 top
C55 "C0603X5R0J104K" 0201 1124.02,1590.74 r270 bottom
C56 "C0603X5R0J104K" 0201 1183.07,1605.74 r270 bottom
C57 "C0603X5R0J104K" 0201 1163.39,1089.26 r90 bottom
C58 "C0603X5R0J104K" 0201 1124.02,1089.26 r90 bottom
C59 "293D106X0010B2TE3" 3528-21 814,1158 r90 bottom
C60 "C1608X5R1A105K" 0603L 1291.34,1089.26 r270 top
C61 "C1608X5R1A105K" 0603L 1291.34,1590.74 r90 top
C62 "C0603X5R0J104K" 0201 1261.81,1089.26 r90 bottom
C63 "C0603X5R0J104K" 0201 1320.87,1089.26 r90 bottom
C64 "C0603X5R0J104K" 0201 1414.13,1221.89 r180 bottom
C65 "C0603X5R0J104K" 0201 1414.13,1280.95 r180 bottom
C66 "C0603X5R0J104K" 0201 1414.13,1340 r180 bottom
C67 "C0603X5R0J104K" 0201 1414.13,1399.05 r180 bottom
C68 "C0603X5R0J104K" 0201 1414.13,1458.11 r180 bottom
C69 "C0603X5R0J104K" 0201 1320.87,1590.74 r270 bottom
C70 "C0603X5R0J104K" 0201 1261.81,1590.74 r270 bottom
C71 "C0603X5R0J104K" 0201 1202.76,1529.51 r90 top
C72 "293D106X0010B2TE3" 3528-21 1424.39,1511.4 r0 top
C73 "C1608X7R1C105K" 0603L 2332.8,1465 r90 top
C74 "0603YC104JAT2A" 0603L 2641.2,1465 r270 top
C75 "GRM1555C1E101JA01D" 0402L 1819.93,1540 r0 top
C76 "C0603C101J5GACTU" 0603L 2149.14,1647.41 r180 top
C77 "C0603C101J5GACTU" 0603L 2107.14,1789.58 r180 top
C78 "C0603C101J5GACTU" 0603L 2021.52,1764.4 r0 bottom
C79 "0603YC104JAT2A" 0603L 2149.14,1694.8 r0 top
C80 "C1608X5R1A106M" 0603L 2145.86,1441.29 r90 top
C81 "LMK212BJ226MG-T" 0805L 2206.12,1441.29 r270 top
C82 "C1608X5R1A106M" 0603L 2025.33,1441.29 r90 top
C83 "LMK212BJ226MG-T" 0805L 2085.59,1441.29 r270 top
C84 "C0603C225K8PACTU" 0603L 1976.07,1441.29 r90 top
C85 "C0603C103K1RACTU" 0603L 1926.81,1441.29 r90 top
C86 "C1608C0G1H152J" 0603L 1834.31,2038.14 r90 top
C87 "C0603C104K5RACTU" 0603L 1877.54,1441.29 r90 top
C88 "C0603C101J5GACTU" 0603L 1938.95,1782.54 r270 bottom
C89 "C0603C101J5GACTU" 0603L 1902.35,1890.31 r90 top
C90 "C0603C223K3RACTU" 0603L 1909.95,2010.58 r0 top
C91 "C0603C101J5GACTU" 0603L 2021.52,1664.57 r180 bottom
C92 "06031C681JAT2A" 0603L 1882.39,2084.81 r90 top
C93 "C0603C101J5GACTU" 0603L 1754.18,1759.72 r90 bottom
C94 "C0603C101J5GACTU" 0603L 1826.34,1514.27 r180 bottom
C95 "GRM1555C1E101JA01D" 0402L 1784.89,1770.79 r270 top
C96 "GRM1555C1E101JA01D" 0402L 1629.91,1703.27 r180 top
C97 "GRM1555C1E101JA01D" 0402L 1629.91,1627.27 r180 top
C98 "C0603C101J5GACTU" 0603L 1716.52,1552.1 r180 bottom
C99 "C0603C101J5GACTU" 0603L 1688.96,1806 r270 bottom
C100 "GRM1555C1E101JA01D" 0402L 1629.91,1593.27 r0 top
C101 "GRM1555C1E101JA01D" 0402L 1629.91,1737.27 r0 top
C102 "C1005X7R1C103K" 0402L 1153.09,1977.24 r90 bottom
C103 "C1005X5R1A104K" 0402L 1293.32,1999.36 r180 bottom
C104 "C1005X5R1A104K" 0402L 1119.92,2439.81 r270 bottom
C105 "C1005X5R1A104K" 0402L 1212.14,2316.76 r270 bottom
C106 "C1005X5R1A104K" 0402L 1293.32,2078.1 r180 bottom
C107 "C1005X5R1A104K" 0402L 1085.92,2439.81 r270 bottom
C108 "C1608X5R1C105K" 0603L 953.92,2316.76 r270 bottom
C109 "C1005X5R1A104K" 0402L 1117.72,1977.24 r90 bottom
C110 "C1005X5R1A104K" 0402L 1034.98,2316.76 r270 bottom
C111 "C1005X5R1A104K" 0402L 1293.32,2176.53 r180 bottom
C112 "C1005X5R1A104K" 0402L 1224.67,2437 r90 bottom
C113 "C1005X5R1A104K" 0402L 1258.67,2437 r90 bottom
C114 "C1005X5R1A104K" 0402L 1258.67,2437 r270 top
C115 "0603YC104JAT2A" 0603L 2669.49,1026 r0 bottom
C116 "06033C104JAT2A" 0603L 2525,2215 r90 top
C117 "06035A331JAT2A" 0603L 2883,2065 r270 top
C118 "C0603X5R0J104K" 0201 2434.72,215.03 r0 top
C119 "C0603X5R0J104K" 0201 2662.47,210.03 r0 top
C120 "C1005X5R1A104K" 0402L 953.8,2215.9 r0 bottom
C121 "C1005X5R1A104K" 0402L 953.8,1999.36 r0 bottom
C122 "C0805C106K8PACTU" 0805L 1106.9,1852.74 r270 top
C123 "C1005X5R1A104K" 0402L 1224.67,2437 r90 top
C124 "C1005X5R1A104K" 0402L 1157.3,1857.74 r270 top
C125 "C1608X5R1A105K" 0603L 2669.49,1026 r0 top
C126 "06033C104JAT2A" 0603L 2982.13,2150 r0 top
C127 "C0603C475K8PACTU" 0603L 3147.49,2090 r180 bottom
C128 "06031C103MAT2A" 0603L 3147.49,1940 r180 bottom
C129 "06033C104JAT2A" 0603L 3734.68,502.06 r180 top
C130 "06033C104JAT2A" 0603L 3822,490.31 r90 top
C131 "C0603X5R0J104K" 0201 2789.45,558.42 r90 top
C132 "C0603X5R0J104K" 0201 2523.31,781.24 r0 top
C133 "C0603X5R0J104K" 0201 2193.45,419.1 r180 top
C134 "C0603X5R0J104K" 0201 2773.45,394.5 r270 top
C135 "GRM1555C1H180JA01D" 0402L 2209.97,926 r180 top
C136 "C0603X5R0J104K" 0201 2336,795.02 r90 top
C137 "GRM1555C1H180JA01D" 0402L 2122.98,926 r0 top
C138 "GRM31CR60J107ME39L" 1206L 110.24,660.39 r270 bottom
C139 "C1608X5R1A106M" 0603L 2206.75,477.1 r180 bottom
C140 "C0603X5R0J104K" 0201 2193.45,468.32 r180 top
C141 "C1608X5R1A106M" 0603L 2236,606 r180 bottom
C142 "C0603X5R0J104K" 0201 2193.45,566.74 r180 top
C143 "C1608X5R1A105K" 0603L 3766.7,622 r0 top
C144 "06033C104JAT2A" 0603L 3575,1890 r0 bottom
C145 "EMK212BJ106KG-T" 0805L 4297,1262 r270 bottom
C146 "EMK212BJ106KG-T" 0805L 4297,1262 r270 top
C147 "06033C104JAT2A" 0603L 4356,1262 r270 top
C148 "06033C104JAT2A" 0603L 4457.27,1394 r270 top
C149 "06035A331JAT2A" 0603L 3671,2065 r270 top
C150 "C1608X5R1A106M" 0603L 3668,2150 r180 top
C151 "06033C104JAT2A" 0603L 3770.13,2150 r0 top
C152 "C1608X5R1A106M" 0603L 3575,1890 r0 top
C153 "06033C104JAT2A" 0603L 2570,1915 r270 top
C154 "06035A100JAT2A" 0603L 4437.44,1044 r180 top
C155 "C1608X5R1C105K" 0603L 4546,1044 r0 top
C156 "GRM31CR60J476ME19L" 1206L 4665,1658.75 r180 top
C157 "GRM31CR60J476ME19L" 1206L 4665,1658.75 r180 bottom
C158 "C1608X5R1A106M" 0603L 4668.94,1802 r180 bottom
C159 "06033C104JAT2A" 0603L 4668.94,1802 r180 top
C160 "C0603C475K8PACTU" 0603L 3935.49,2090 r180 bottom
C161 "06031C103MAT2A" 0603L 3935.49,1940 r180 bottom
C162 "GRM188R71E332KA01D" 0603L 4650,1109.54 r0 top
C163 "C1608X5R1A106M" 0603L 2570,1915 r270 bottom
C164 "06033C104JAT2A" 0603L 2597,2345.06 r90 top
C165 "C1608X5R1A106M" 0603L 2597,2345.06 r90 bottom
C166 "C1608X5R1A106M" 0603L 2880,2150 r180 top
C167 "06033C104JAT2A" 0603L 3520,1319.27 r270 top
C168 "C1608X7R1C224K" 0603L 3496,1716 r90 top
C169 "GRM155R60J104KA01D" 0402L 3593.74,1361 r270 top
C170 "GRM155R60J104KA01D" 0402L 3446.26,1361 r90 top
C171 "C1608X5R1A106M" 0603L 2525,2215 r90 bottom
C172 "C1608X5R1A106M" 0603L 3065.67,2437 r90 top
C173 "EMK212BJ106KG-T" 0805L 3479.5,1319.27 r270 bottom
C174 "GRM188R71C273KA01D" 0603L 3688,1716 r90 top
C175 "GRM188R71C273KA01D" 0603L 3352,1716 r270 top
C176 "06033C104JAT2A" 0603L 2964.41,1084 r0 top
C177 "06033C104JAT2A" 0603L 2378.44,2341.5 r180 top
C178 "06033C393KAT2A" 0603L 3592,1716 r90 top
C179 "06033C393KAT2A" 0603L 3448,1716 r90 top
C180 "GRM31CR61A226ME19L" 1206L 4098,1283 r180 top
C181 "GRM31CR61A226ME19L" 1206L 4098,1283 r180 bottom
C182 "GRM31CR61A226ME19L" 1206L 2990,1283 r0 top
C183 "GRM31CR61A226ME19L" 1206L 2990,1283 r0 bottom
C184 "EMK212BJ106KG-T" 0805L 3560.5,1319.27 r270 bottom
C185 "06033C104JAT2A" 0603L 2773.68,2418 r270 top
C186 "C1608X5R1A106M" 0603L 3065.68,2539 r270 top
C187 "06035A561JAT2A" 0603L 2872.68,2558.87 r270 bottom
C188 "C1608X5R1A106M" 0603L 2317,2406.01 r180 top
C189 "06033C104JAT2A" 0603L 2521.56,2341.5 r0 top
C190 "C1608X5R1A106M" 0603L 2964.41,1084 r0 bottom
C191 "06033C104JAT2A" 0603L 4118.5,2513.93 r270 top
C192 "GRM188R71C472KA01D" 0603L 3814,2536.39 r90 top
C193 "EEE-FC1E101P" SM_RADIAL_F 1785,191.6 r0 top
C194 "GRM32DC81E106KA12L" 1210L 1778,73.49 r180 bottom
C195 "C1608X5R1A106M" 0603L 2773.68,2418 r270 bottom
C196 "C1608X5R1A106M" 0603L 3814,2402.53 r90 top
C197 "C1608X5R1A106M" 0603L 2521.56,2292.5 r0 top
C198 "06033C104JAT2A" 0603L 3862,2536.39 r90 top
C199 "06033C104JAT2A" 0603L 4123.59,1084 r180 top
C200 "C1608X5R1A106M" 0603L 2689.26,789.7 r0 top
C201 "C1608X5R1C105K" 0603L 329.24,689.56 r270 bottom
C202 "C1608X5R1A106M" 0603L 4118.5,2513.93 r270 bottom
C203 "C1608X5R1A106M" 0603L 4123.59,1084 r180 bottom
C204 "C1608X5R1A106M" 0603L 3862,2536.39 r90 bottom
C205 "C1608X5R1A105K" 0603L 2620.12,475 r180 bottom
C206 "C1005X5R1A104K" 0402L 1271.2,2316.76 r270 bottom
C207 "C1005X5R1A104K" 0402L 1153.09,2316.76 r270 bottom
C208 "C1005X5R1A104K" 0402L 1094.03,2316.76 r270 bottom
C209 "C1005X5R1A104K" 0402L 995.61,2316.76 r270 bottom
C210 "0603YC104JAT2A" 0603L 111.3,839 r0 bottom
C211 "C1608X5R1C105K" 0603L 228.7,775.86 r0 bottom
C212 "GRM31CR60J107ME39L" 1206 2598,846 r0 bottom
C213 "GRM1555C1E101JA01D" 0402L 1767.87,1570.41 r90 top
C214 "C0603X5R0J104K" 0201 2605.59,781.24 r180 top
C215 "GRM155R71A104KA01D" 0402L 1498,1726 r180 top
C216 "GRM155R71A104KA01D" 0402L 1786,1840 r0 top
C217 "GRM155R71A104KA01D" 0402L 2715.55,1790 r180 top
C218 "GRM155R71A104KA01D" 0402L 2200,1040 r180 top
C219 "GRM155R71A104KA01D" 0402L 2873.85,1090 r180 top
C220 "GRM155R71A104KA01D" 0402L 3138,990 r0 bottom
C221 "GRM155R71A104KA01D" 0402L 3053,1090 r0 bottom
C222 "GRM155R71A104KA01D" 0402L 4219,1090 r0 top
C223 "GRM155R71A104KA01D" 0402L 3791,1090 r180 bottom
C224 "GRM155R71A104KA01D" 0402L 2869,1790 r180 bottom
C225 "GRM155R71A104KA01D" 0402L 3053,1790 r0 bottom
C226 "GRM155R71A104KA01D" 0402L 4007,1790 r0 bottom
C227 "GRM155R71A104KA01D" 0402L 3791,1790 r180 bottom
C228 "500R07S0R5BV4T" 0402L 730.85,1504.45 r270 bottom
C229 "500R07S0R5BV4T" 0402L 730.85,1431.46 r90 bottom
D2 "1N4148W-7-F" SOD-123 2282.48,1165 r180 bottom
D4 "1N4148W-7-F" SOD-123 2282.48,1115 r180 top
D11 "MBRS540T3G" SMC 3764,1191 r0 top
D12 "MBRS540T3G" SMC 3276,1191 r180 top
DEVCLK "SASF546-P26-X1" CONN_LTI_SASF546-P26-X1 408.31,2289 r0 top
EXT5V_FMC12V "PBC03SAAN" PBC03SAAN 4411,90 r0 top (schematic designator +12V)
FID1 "Fiducial" Fiducial10-30 341,2592 r0 top
FID2 "Fiducial" Fiducial10-30 88,478 r0 top
FID3 "Fiducial" Fiducial10-30 5316,2592 r0 top
FLout "TESTPOINT" TESTPOINT 2068,2179 r0 top
FMC_RX1 "ASP-134488-01" CONN_SEARAY_ASP-134488-01 5084,1341.94 r90 bottom locked
FTDI_3P3V "TSW-103-07-G-S" TSW-103-07-G-S 1617.28,426 r180 top
GND "5011" Keystone5011 336.21,1945 r0 top
GND1 "5011" Keystone5011 2256,2576 r0 top
GND2 "5011" Keystone5011 4713,95 r0 top
GND3 "5011" Keystone5011 4312,2526 r0 top
H3 "1902A" Keystone_1902C 542,580 r180 bottom
H4 "1902A" Keystone_1902C 1843.5,2505 r180 bottom
H5 "NY PMS 440 0025 PH" "NY PMS 440 0025 PH"#1 542,580 r0 top
H6 "NY PMS 440 0025 PH" "NY PMS 440 0025 PH"#2 1843.5,2505 r0 top
J1 "TSW-104-07-G-S" TSW-104-07-G-S 3617,690 r270 top
J3 "TSW-102-07-G-S" TSW-102-07-G-S 3066,690 r90 top
"KC705 JTAG" "TSW-102-07-G-S" TSW-102-07-G-S 4575,915 r180 top
L1 "BLM18SG121TN1D" 0603 1751,1642.5 r270 bottom
L2 "BLM18SG331TN1D" 0603 1342.42,1932.5 r180 bottom
L3 "BLM18SG331TN1D" 0603 1170.95,2428 r270 bottom
L4 "BLM18SG331TN1D" 0603 1373.92,2035.92 r90 bottom
L5 "BLM18SG331TN1D" 0603 1034.98,2428 r270 bottom
L6 "BLM18SG260TN1D" 0603 3485,1908 r270 top
L7 "BLM18SG121TN1D" 0603 4665,1739.21 r0 top
L8 "CDRH6D28NP-3R0NC" CDRH6D28 4414,1614 r90 top
L9 "BLM18SG260TN1D" 0603 2665.5,1940 r180 top
L10 "BLM18SG260TN1D" 0603 2597,2134.5 r90 top
L11 "MSS1038-702NLB" MSS1038 3984,1571 r180 top
L12 "744325550" WE-HC6 3033,1571 r180 top
L13 "BLM18SG260TN1D" 0603 2525,2071.5 r90 top
L14 "BLM18SG121TN1D" 0603 2936.85,1175 r270 top
L15 "BLM18SG260TN1D" 0603 2406,2437.5 r270 top
L16 "BLM18SG260TN1D" 0603 2494,2437.5 r270 top
L17 "BLM18SG260TN1D" 0603 1799.65,191.6 r0 bottom
L18 "BLM18SG260TN1D" 0603 4082,2602.93 r0 top
L19 "BLM18SG331TN1D" 0603 1373.92,2218.71 r270 bottom
L20 "BLM18SG121TN1D" 0603 4151.15,1175 r270 top
L21 "BLM18SG331TN1D" 0603 875.5,2247.39 r270 bottom
L22 "BLM18SG331TN1D" 0603 875.5,2030.86 r270 bottom
L23 "BLM18SG331TN1D" 0603 2831,251 r0 top
L24 "BLM18SG121TN1D" 0603 2324,491 r180 bottom
L25 "BLM18SG121TN1D" 0603L 2263.56,682 r270 bottom
L26 "BLM18SG260TN1D" 0603 115.24,775.86 r180 bottom
LBL1 "Size: 0.65\" x 0.20 \"" Label_650x200 4490,2178 r90 bottom
LD "LTST-C190GKT" LED_LTST-C190 2299.5,1240 r0 top
LD1 "TESTPOINT" TESTPOINT 1587.93,2181 r270 top
LD2 "TESTPOINT" TESTPOINT 724,2561 r180 top
LF1 "C1608C0G1E392J" 0603L 955.3,2436.74 r180 top
LF2 "06035A470JAT2A" 0603L 955.3,2386.74 r180 top
LF3 "RC0603FR-07619RL" 0603L 875.86,2409.18 r90 top
LF7 "ACM7060-301-2PL-TL" IND_TDK_ACM7060 1498.5,153.54 r0 bottom
LMK_INT "TSW-102-07-G-S" TSW-102-07-G-S 3310,2040 r180 top
LMK_LDO "TSW-102-07-G-S" TSW-102-07-G-S 2747,2040 r180 top
LMKCLK "SASF546-P26-X1" CONN_LTI_SASF546-P26-X1 1517.5,2502 r0 top
LMX_INT "TSW-102-07-G-S" TSW-102-07-G-S 4098,2040 r180 top
LMX_LDO "TSW-102-07-G-S" TSW-102-07-G-S 3535,2040 r180 top
Logo1 "ESD Susceptible" ESD_Overlay_Small 4519,1930 r0 top
Logo2 "Texas Instruments" TI_Symbol_Overlay_Small 4305,2277 r0 top
MUX "TESTPOINT" TESTPOINT 1931,2230 r315 top
MUXout "LTST-C190GKT" LED_LTST-C190 2196.5,1819 r90 top
NCO "TSW-103-07-G-D" TSW-103-07-G-D 1871.5,1140 r0 top
OR "TSW-103-07-G-S" TSW-103-07-G-S 1555.5,2015 r180 top
OR_T0 "LTST-C190KFKT" LED_LTST-C190 2678,1232.52 r0 top
OR_T1 "LTST-C190KFKT" LED_LTST-C190 2678,1090 r0 top
OSCin "SASF546-P26-X1" CONN_LTI_SASF546-P26-X1 2280.38,2128 r0 top
PG_RX1 "TSW-102-07-G-S" TSW-102-07-G-S 4609,2559 r180 top
R1 "CRCW04028K06FKED" 0402L 2561,1140 r0 bottom
R2 "CRCW04021K20JNED" 0402L 2707.53,1212.84 r270 bottom
R3 "CRCW04021M00JNED" 0402L 2452,1254.36 r0 bottom
R4 "CRCW060310K0FKEA" 0603L 2083.5,1090 r180 top
R5 "CRCW060310K0FKEA" 0603L 1871.5,1004 r90 bottom
R6 "CRCW060310K0FKEA" 0603L 1771.5,1004 r90 bottom
R7 "ERJ-1GE0R00C" 0201 1583.2,1224.93 r90 bottom
R8 "ERJ-1GE0R00C" 0201 1493.2,1165.87 r90 bottom
R9 "ERJ-1GE0R00C" 0201 1264.85,1010.18 r0 bottom
R10 "CRCW04021K20JNED" 0402L 2707.53,1109.68 r90 bottom
R11 "CRCW04021M00JNED" 0402L 2407.32,950 r0 top
R12 "CRCW04021K33FKED" 0402L 2482.32,1122 r0 bottom
R13 "RG1608P-332-B-T5" 0603L 936.26,1175 r180 top
R14 "CRCW060310K0FKEA" 0603L 1731.28,858.81 r0 top
R15 "CRCW060310K0FKEA" 0603L 1731.28,811.41 r0 top
R16 "CRCW060310K0FKEA" 0603L 1731.28,763.41 r0 top
R17 "RC0603JR-07750RL" 0603L 1731.28,763.41 r0 bottom
R18 "ERJ-1GE0R00C" 0201 1080.99,1694 r90 bottom
R19 "ERJ-1GE0R00C" 0201 1080.99,1694 r90 top
R20 "ERJ-1GE0R00C" 0201 1107.99,1694 r90 top
R21 "ERJ-1GE0R00C" 0201 1107.99,1694 r90 bottom
R22 "ERJ-1GE0R00C" 0201 1094,1653 r0 top
R23 "ERJ-1GE0R00C" 0201 1135,1666 r270 top
R24 "CRCW06030000Z0EA" 0603L 2283.8,1465 r270 top
R25 "CRCW060318R0JNEA" 0603L 2278.38,1770 r90 top
R26 "CRCW06039K09FKEA" 0603L 2641.2,1465 r270 bottom
R27 "CRCW060356R0JNEA" 0603L 2305.94,1646.56 r0 top
R28 "CRCW060368R0JNEA" 0603L 2352.82,1694.8 r180 top
R29 "CRCW060318R0JNEA" 0603L 2250.82,1694.8 r180 top
R30 "CRCW06030000Z0EA" 0603L 2407.94,1743 r0 top
R31 "RC0603JR-071K3L" 0603L 1731.28,811.41 r0 bottom
R32 "RC0603JR-071K3L" 0603L 1731.28,858.81 r0 bottom
R33 "RC0603FR-07430RL" 0603L 1984.18,2084.81 r90 top
R34 "RC0603FR-07430RL" 0603L 2011.74,2010.58 r180 top
R35 "CRCW040251R0JNED" 0402L 1669.28,1627.27 r0 bottom
R36 "CRCW040251R0JNED" 0402L 1669.28,1593.27 r180 bottom
R37 "CRCW040251R0JNED" 0402L 1669.28,1737.27 r0 bottom
R38 "CRCW040251R0JNED" 0402L 1669.28,1703.27 r180 bottom
R39 "RC0603JR-071KL" 0603L 2856,1940 r0 top
R40 "CSNL1206FT2L00" 1206 2747,2135.44 r180 bottom
R41 "CRCW060310K7FKEA" 0603L 2883,2065 r90 bottom
R42 "CSNL1206FT2L00" 1206 3310,2135.44 r180 bottom
R43 "CRCW04020000Z0ED" 0402L 833.56,2130 r180 top
R44 "CRCW04020000Z0ED" 0402L 833.56,2164 r180 top
R45 "CRCW0603270RJNEA" 0603L 826.5,2625 r0 top
R46 "RC0603JR-071K3L" 0603L 2145.79,1600.02 r0 top
R47 "RC0603FR-072K32L" 0603L 1057.79,1890 r180 bottom
R48 "CRCW04020000Z0ED" 0402L 1281.67,2502 r0 top
R49 "RC0603FR-074K64L" 0603L 2958,2037.44 r180 bottom
R50 "" 0402L 1224.67,2521.68 r90 top
R51 "CRCW040251R0JNED" 0402L 1338.67,2521.68 r270 top
R52 "CRCW060310R0JNEA" 0603L 957.8,531.69 r0 top
R53 "CRCW060310R0JNEA" 0603L 957.8,483.69 r0 top
R54 "CRCW0603100RJNEA" 0603L 3925.56,263.94 r270 bottom
R55 "CRCW0603100RJNEA" 0603L 3870.44,263.94 r270 bottom
R56 "CRCW0603270RJNEA" 0603L 1653.5,2267.95 r180 top
R57 "CRCW0603100RJNEA" 0603L 3870.44,487.44 r90 bottom
R58 "CRCW0603100RJNEA" 0603L 3925.56,466.06 r90 bottom
R59 "CRCW04020000Z0ED" 0402L 1413.56,2164 r0 top
R60 "CRCW04020000Z0ED" 0402L 1413.56,2130 r0 top
R61 "CRCW04020000Z0ED" 0402L 1238.98,1857 r270 top
R62 "CRCW04020000Z0ED" 0402L 1204.98,1857 r270 top
R63 "CRCW04020000Z0ED" 0402L 1002.76,1857 r270 top
R64 "CRCW04020000Z0ED" 0402L 968.76,1857 r270 top
R65 "CRCW0603100RJNEA" 0603L 3734.68,229 r0 top
R66 "CRCW06031K00FKEA" 0603L 2173.47,351.73 r180 top
R67 "RC0603FR-0712KL" 0603L 2121.47,575.52 r270 top
R68 "CRCW0603100RJNEA" 0603L 2988.44,440 r180 top
R69 "CRCW0603100RJNEA" 0603L 3091,440 r0 bottom
R70 "RC0603JR-0710KL" 0603L 4391.19,1164.85 r270 bottom
R71 "RC0603JR-071KL" 0603L 3644,1940 r0 top
R72 "CRCW060382K5FKEA" 0603L 4437.44,995 r0 top
R73 "CSNL1206FT2L00" 1206 3535,2135.44 r180 bottom
R74 "CRCW060310K7FKEA" 0603L 3671,2065 r90 bottom
R75 "CSNL1206FT2L00" 1206 4098,1944.56 r180 bottom
R76 "CRCW060322K1FKEA" 0603L 4546,995 r180 top
R77 "RC0603FR-074K64L" 0603L 3746,2037.44 r180 bottom
R78 "RC0603FR-0710RL" 0603L 3544,1716 r270 top
R79 "CRCW0603732RFKEA" 0603L 3114.68,2539 r270 top
R80 "RC0603JR-071KL" 0603L 3030.66,2631 r180 top
R81 "CRCW060316K2FKEA" 0603L 3688,1716 r270 bottom
R82 "CRCW06037K87FKEA" 0603L 3352,1716 r90 bottom
R83 "CSNL1206FT2L00" 1206 2945.26,2209.56 r0 bottom
R84 "CSNL1206FT2L00" 1206 2638.27,2564.44 r180 bottom
R85 "CRCW06032K49FKEA" 0603L 2773.68,2520 r270 top
R86 "CRCW06035K90FKEA" 0603L 3640,1716 r270 top
R87 "CRCW06035K90FKEA" 0603L 3400,1716 r270 top
R88 "CRCW06034K99FKEA" 0603L 2797.68,2547.56 r180 bottom
R89 "CRCW06032K80FKEA" 0603L 2975.36,2558.87 r90 bottom
R90 "RC0603FR-07402RL" 0603L 3065.68,2539 r90 bottom
R92 "CSNL1206FT2L00" 1206 4045.44,2552.93 r90 bottom
R93 "RC0603FR-071KL" 0603L 3814,2536.39 r270 bottom
R94 "CRCW12061K00JNEA" 1206L 4411,289 r270 top
R95 "CSNL1206FT2L00" 1206 3994.44,2319.07 r90 bottom
R96 "RC0603FR-07357RL" 0603L 3838,2612 r180 top
R97 "CRCW060312K4FKEA" 0603L 3091,540 r0 top
R98 "CRCW060312K4FKEA" 0603L 3091,440 r0 top
R99 "CRCW0603270RJNEA" 0603L 2149.14,1742.19 r0 top
R100 "CRCW0603270RJNEA" 0603L 2195.5,1240 r0 top
R101 "CRCW060312K4FKEA" 0603L 3091,340 r0 top
R102 "CRCW060312K4FKEA" 0603L 3091,240 r0 top
R103 "CRCW06030000Z0EA" 0603L 329.24,811.96 r270 bottom
R104 "CRCW040224K0JNED" 0402L 3083.13,398 r180 top
R105 "CRCW060310K0FKEA" 0603L 2482.32,735 r90 bottom
R106 "CRCW060310K0FKEA" 0603L 2419.2,815 r90 top
R107 "CRCW060310K0FKEA" 0603L 2371.2,815 r90 top
R108 "RC0603JR-072K2L" 0603L 2509.88,659 r180 bottom
R109 "CRCW0603100RJNEA" 0603L 3898,438.5 r180 top
R110 "CRCW0603100RJNEA" 0603L 3898,340.5 r180 top
R111 "CRCW0603100RJNEA" 0603L 3898,389.5 r180 top
R112 "CRCW0603270RJNEA" 0603L 2081.91,273.24 r270 top
R113 "CRCW0603100RJNEA" 0603L 2989,540 r180 top
R114 "CRCW0603100RJNEA" 0603L 2988.44,298 r180 top
R115 "CRCW0603100RJNEA" 0603L 3035.88,157.56 r180 top
R116 "CRCW040224K0JNED" 0402L 3036.24,498 r180 top
R117 "RC0603JR-071K3L" 0603L 2092.31,1938 r0 top
R118 "CRCW0603100RJNEA" 0603L 3898,291.5 r180 top
R119 "CRCW0603100RJNEA" 0603L 3091,540 r0 bottom
R120 "CRCW0603100RJNEA" 0603L 3091,340 r0 bottom
R121 "CRCW0603100RJNEA" 0603L 3091,240 r0 bottom
R122 "RC0603JR-071K3L" 0603L 1028.93,1966.24 r270 bottom
R123 "CRCW060310K0FKEA" 0603L 3822,290.53 r270 top
R124 "CRCW0603100RJNEA" 0603L 2828,369.57 r270 top
R125 "CRCW0603100RJNEA" 0603L 2879.56,369.57 r270 top
R126 "CRCW0603100RJNEA" 0603L 2856,445 r0 top
R127 "CRCW0603100RJNEA" 0603L 2907.12,397.13 r0 bottom
R128 "CRCW040224K0JNED" 0402L 3083.13,298 r180 top
R129 "CRCW040224K0JNED" 0402L 3083.13,282 r180 bottom
R130 "CRCW060310K0FKEA" 0603L 2871,522.46 r270 bottom
R131 "CRCW060310K0FKEA" 0603L 2822,542.15 r270 bottom
R132 "CRCW06030000Z0EA" 0603L 4691,515 r0 top
R133 "CRCW06031K00FKEA" 0603L 2668.76,1387.81 r0 top
R134 "RC0603JR-071KL" 0603L 1404.8,1699 r180 bottom
R135 "CRCW06032K10FKEA" 0603L 1377.24,1624 r90 bottom
R136 "CRCW06034K70JNEA" 0603L 1821.5,1302 r90 top
R137 "CRCW06034K70JNEA" 0603L 1949.06,1276 r0 top
R138 "CRCW06034K70JNEA" 0603L 2083.5,1041 r0 top
R139 "CRCW06032K00JNEA" 0603L 4184.44,292.56 r270 bottom
R140 "CRCW06032K00JNEA" 0603L 4184.44,392.56 r270 bottom
R141 "CRCW06032K00JNEA" 0603L 4184.44,492.56 r270 bottom
R142 "CRCW06030000Z0EA" 0603L 2094.06,1540 r0 bottom
R143 "CRCW06030000Z0EA" 0603L 2149.14,1742.19 r0 bottom
RR6 "CRCW06034K99FKEA" 0603L 4986.56,2340 r180 top
RR7 "ERJ-3GEY0R00V" 0603L 4934,390 r180 top
RSV "TSW-103-07-G-S" TSW-103-07-G-S 1045.28,702 r0 top
S1 "L101011MS02Q" "SW_ L101011MS02Q" 1065,212.6 r270 top
SH-1V2ADC_INT_1_2 "SNT-100-BK-G" SNT-100-BK-G 2945.26,2305 r180 top
SH-1V2ADC_LDO_1_2 "SNT-100-BK-G" SNT-100-BK-G 2638.27,2469 r180 top
SH-1V9ADC_1_2 "SNT-100-BK-G" SNT-100-BK-G 3950,2552.93 r90 top
SH-1V9INT_1_2 "SNT-100-BK-G" SNT-100-BK-G 3899,2319.07 r90 top
SH-5V_12V_1_2 "SNT-100-BK-G" SNT-100-BK-G 4361,90 r180 top
SH-FTDI_3P3V_1_2 "SNT-100-BK-G" SNT-100-BK-G 1567.28,426 r0 top
SH-LMK_INT_1_2 "SNT-100-BK-G" SNT-100-BK-G 3310,2040 r180 top
SH-LMK_LDO_1_2 "SNT-100-BK-G" SNT-100-BK-G 2747,2040 r180 top
SH-LMX_INT_1_2 "SNT-100-BK-G" SNT-100-BK-G 4098,2040 r180 top
SH-LMX_LDO_1_2 "SNT-100-BK-G" SNT-100-BK-G 3535,2040 r180 top
SH-RSV_1_2 "969102-0000-DA" SNT-100-BK-G 995.28,702 r180 top
"SH-Ts ADD1_1_2" "969102-0000-DA" SNT-100-BK-G 1667.28,653 r180 top
SPI "TSW-104-07-G-D" TSW-104-07-G-D 4061,365 r90 top
Status1 "LTST-C190GKT" LED_LTST-C190 1523.5,2274.95 r0 top
Status2 "LTST-C190GKT" LED_LTST-C190 824.53,2561 r0 top
T1 "B0430J50100AHF" B0430J50100AHF 713.33,1330.16 r0 bottom
T2 "TCM2-43X+" Mini-Circuits-DB1627 605.65,1467.95 r270 bottom
TCRIT1 "TESTPOINT" TESTPOINT 1836.28,653 r270 top
TCRIT2 "TESTPOINT" TESTPOINT 1939.5,725 r270 top
TCRIT3 "TESTPOINT" TESTPOINT 1703.72,937 r270 top
Tdiode "TSW-102-07-G-S" TSW-102-07-G-S 1270.28,777 r270 top
TEMP "LTST-C170KRKT" LED_LTST-C170 1833.28,817.94 r270 top
TMST+ "142-0701-806" Johnson_142-0701-80x 100,1830.16 r270 bottom
TMST- "142-0701-806" Johnson_142-0701-80x 100,2330.16 r270 bottom
TP_LD "TESTPOINT" TESTPOINT 2096.5,1190 r315 top
"Ts ADD1" "TSW-103-07-G-S" TSW-103-07-G-S 1617.28,653 r180 top
U1 "LMC6762AIMX" M08A_L 2502,1140 r270 top
U2 "ADC12J4000RLY" RLY0068A 1163.39,1340 r0 bottom
U3 "LM95233CISD/NOPB" SDA14B 1546.28,796.76 r0 top
U4 "LMX2581SQ/NOPB" RTV0032A 1931.87,1684.96 r270 top
U5 "LP3878MR-ADJ/NOPB" MRA08A_N 3053,2015 r180 top
U6 "LMK04828BISQ/NOPB" NKD0064A 1123.56,2147 r90 top
U7 "TPS54327DDA" DDA0008B_L 4490,1206 r90 top
U8 "LP3878MR-ADJ/NOPB" MRA08A_N 3841,2015 r180 top
U9 "LM26400YSDE/NOPB" SDA16A 3520,1524 r270 top
U10 "TPS74901RGW" RGW0020A 2919.68,2488 r90 top
U11 "LP38513TJ-ADJ/NOPB" TJ5A_N 3482,2436 r180 top
U12 "SN74AVC4T774PW" PW0016A_L 3652,365.53 r0 top
U13 "FT4232HL" LQFP64_N 2500.47,488 r0 top
U14 "TLV70233DBV" DBV0005A_N 228.7,670.86 r180 bottom
U15 "93LC46B-I/MS" MSOP-MS8_N 2565,567 r0 bottom
U16 "24C65T/SM" SOIJ-SM8_N 3873,765 r180 top
USB "651-305-142-821" CONN_USB-MINI-AB-651-305-142-821 220.47,782.44 r270 top
USB_PWR "LTST-C190GKT" LED_LTST-C190 2145.91,275.2 r270 top
uWIRE "N2510-6002-RB" CONN_2510-6002 3321,440 r90 top
VA12 "TSW-102-07-G-S" TSW-102-07-G-S 2126,2431 r180 top
VA19 "TSW-102-07-G-S" TSW-102-07-G-S 1145.28,927 r90 top
VADJ_RX "5011" Keystone5011 4659,2315 r90 top
Vbg "TSW-102-07-G-S" TSW-102-07-G-S 982.78,927 r90 top
Vcmo "TSW-102-07-G-S" TSW-102-07-G-S 857.78,927 r90 top
VD12 "TSW-102-07-G-S" TSW-102-07-G-S 1423,1078 r180 top
VIN "142-0701-806" Johnson_142-0701-80x 100,1330.16 r270 bottom
VIN+ "SASF546-P26-X1" CONN_LTI_SASF546-P26-X1 580,963.32 r0 top
VIN- "SASF546-P26-X1" CONN_LTI_SASF546-P26-X1 580,1697 r0 top
Vtune "TESTPOINT" TESTPOINT 1762.39,2023 r270 top
Y1 "CWX813-100.0M" OSC_CWX 2487,1520 r180 top
Y2 "ABM3-12.000MHZ-B2-T" XTAL_ABM3 2166.47,827 r180 top
ZZ1 "This Assembly Note is for PCB labels only" AssemblyNoteLabel 185,3938 r0 top
ZZ2 "These assemblies are ESD sensitive, ESD precautions shall be observed." AssemblyNote 185,3829.11 r0 top
ZZ3 "These assemblies must be clean and free from flux and all contaminants. Use of no clean flux is not acceptable." AssemblyNote 185,3740.56 r0 top
ZZ4 "These assemblies must comply with workmanship standards IPC-A-610 Class 2., unless otherwise specified." AssemblyNote 185,3652 r0 top

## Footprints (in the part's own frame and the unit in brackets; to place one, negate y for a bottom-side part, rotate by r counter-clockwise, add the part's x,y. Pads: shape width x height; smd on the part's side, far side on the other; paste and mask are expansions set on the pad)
0201 [mm] "Data from Kemet datasheet CC101_COM dated 7/28/11"
  rect 0.46x0.42 smd mask+0.048: 1(-0.33,0) 2(0.33,0)
  body extent -0.31,-0.16 0.31,0.16, height 0.26
0201L [mm] "Data from Kemet datasheet CC101_COM dated 7/28/11"
  rect 0.36x0.32 smd mask+0.048: 1(-0.28,0) 2(0.28,0)
  body extent -0.31,-0.16 0.31,0.16, height 0.26
0402L [mm] "0402 from SM-752 data"
  rect 0.6x0.5 smd: 1(-0.5,0) 2(0.5,0)
  body extent -0.55,-0.3 0.55,0.3, height 0.6
0603 [mm] "0603 from SM-752 data"
  rect 1x0.95 smd: 1(-0.8,0) 2(0.8,0)
  silkscreen extent -1.52,-0.69 1.52,0.69, body extent -0.87,-0.47 0.87,0.47, height 0.85
0603L [mm] "0603 from SM-752 data"
  rect 0.8x0.85 smd: 1(-0.7,0) 2(0.7,0)
  silkscreen extent -0.07,-0.33 0.07,0.33, body extent -0.87,-0.47 0.87,0.47, height 0.85
0805L [mm] "0805 from SM-752 data"
  rect 1.1x1.4 smd: 1(-0.75,0) 2(0.75,0)
  body extent -1.1,-0.72 1.1,0.72, height 1.1
1206 [mm] "1206 from SM-752 data"
  rect 1.3x1.85 smd: 1(-1.45,0) 2(1.45,0)
  silkscreen extent -2.4,-1.21 2.4,1.21, body extent -1.7,-0.9 1.7,0.9, height 1.35
1206L [mm] "1206 from SM-752 data"
  rect 1.1x1.75 smd: 1(-1.35,0) 2(1.35,0)
  silkscreen extent -0.4,-0.78 0.4,0.77, body extent -1.7,-0.9 1.7,0.9, height 1.35
1210L [mm] "1210 from SM-752 data"
  rect 1.1x2.6 smd: 1(-1.35,0) 2(1.35,0)
  silkscreen extent -0.4,-1.2 0.4,1.2, body extent -1.7,-1.35 1.7,1.35, height 1.35
3528-21 [mm] "Medium Density IPC, based on SM-782 section 8.4"
  rect 1.95x2.25 smd: 1(-1.375,0) 2(1.375,0)
  silkscreen extent -2.66,-1.5 1.9,1.79, body extent -1.85,-1.5 1.85,1.5, height 2.1
AssemblyNote [mil] "Assembly Note"
AssemblyNoteLabel [mil] "Assembly Note for PCB Labels"
B0430J50100AHF [mm] "Anaren Ultra Low Profile 0805 Balun 50  to 100  Balanced"
  rect 0.75x0.41 smd mask+0.073: 1(-0.705,0.66) 2(-0.705,0) 3(-0.705,-0.66) 4(0.705,-0.66) 5(0.705,0) 6(0.705,0.66)
  silkscreen extent -0.69,-1.07 0.69,1.07, body extent -0.69,-1.07 0.69,1.07, height 0.75
CDRH6D28 [mm] "Sumida reommended land pattern"
  rect 2.65x7.3 smd: 1(-2.325,0) 2(2.325,0)
  silkscreen extent -4,-4 4,4, body extent -3.5,-3.5 3.5,3.5, height 3
CONN_2510-6002 [mm] "3M 2500 series TS-0770-L December 15, 2011"
  rect 1.65x1.65 hole 1.016 mask+0: 1(-5.08,-1.27)
  round 1.65 hole 1.016 mask+0: 2(-5.08,1.27) 3(-2.54,-1.27) 4(-2.54,1.27) 5(0,-1.27) 6(0,1.27) 7(2.54,-1.27) 8(2.54,1.27) 9(5.08,-1.27) 10(5.08,1.27)
  silkscreen extent -10.01,-4.17 10.01,4.47, body extent -10.01,-4.11 10.01,4.52, height 9.92
CONN_CUI-PJ-202AH [mm] "Conn_DC Jack"
  oval 1.5x4 hole 1 slot 3.5 at 90 deg: 1(0,0) 2(6,0)
  oval 4x1.5 hole 1 slot 3.5 at 0 deg: 3(3,4.7)
  silkscreen extent -0.7,-4.5 13.7,4.5, body extent -0.7,-4.5 13.7,4.9, height 11.02
CONN_LTI_SASF546-P26-X1 [mm]
  round 0.8 smd: 1(0,0)
  round 2.25 hole 1.5 mask+0.051: 2(-2.54,2.54) 3(-2.54,-2.54) 4(2.54,-2.54) 5(2.54,2.54)
  silkscreen extent -3.4,-3.4 3.4,3.4, body extent -3.17,-3.17 3.17,3.17, height 12.53
CONN_SEARAY_ASP-134488-01 [mm]
  round 0.635 hole 1.27 unplated mask+0.572: 401(27.191,0) 402(-27.191,-3.048)
  round 0.64 smd paste+0.125 mask+0.05: A1(24.716,5.715) A2(23.446,5.715) A3(22.176,5.715) A4(20.906,5.715) A5(19.636,5.715) A6(18.366,5.715) A7(17.096,5.715) A8(15.826,5.715) A9(14.556,5.715) A10(13.286,5.715) A11(12.016,5.715) A12(10.746,5.715) A13(9.476,5.715) A14(8.206,5.715) A15(6.936,5.715) A16(5.666,5.715) A17(4.396,5.715) A18(3.126,5.715) A19(1.856,5.715) A20(0.586,5.715) A21(-0.684,5.715) A22(-1.954,5.715) A23(-3.224,5.715) A24(-4.494,5.715) A25(-5.764,5.715) A26(-7.034,5.715) A27(-8.304,5.715) A28(-9.574,5.715) A29(-10.844,5.715) A30(-12.114,5.715) A31(-13.384,5.715) A32(-14.654,5.715) A33(-15.924,5.715) A34(-17.194,5.715) A35(-18.464,5.715) A36(-19.734,5.715) A37(-21.004,5.715) A38(-22.274,5.715) A39(-23.544,5.715) A40(-24.814,5.715) B1(24.716,4.445) B2(23.446,4.445) B3(22.176,4.445) B4(20.906,4.445) B5(19.636,4.445) B6(18.366,4.445) B7(17.096,4.445) B8(15.826,4.445) B9(14.556,4.445) B10(13.286,4.445) B11(12.016,4.445) B12(10.746,4.445) B13(9.476,4.445) B14(8.206,4.445) B15(6.936,4.445) B16(5.666,4.445) B17(4.396,4.445) B18(3.126,4.445) B19(1.856,4.445) B20(0.586,4.445) B21(-0.684,4.445) B22(-1.954,4.445) B23(-3.224,4.445) B24(-4.494,4.445) B25(-5.764,4.445) B26(-7.034,4.445) B27(-8.304,4.445) B28(-9.574,4.445) B29(-10.844,4.445) B30(-12.114,4.445) B31(-13.384,4.445) B32(-14.654,4.445) B33(-15.924,4.445) B34(-17.194,4.445) B35(-18.464,4.445) B36(-19.734,4.445) B37(-21.004,4.445) B38(-22.274,4.445) B39(-23.544,4.445) B40(-24.814,4.445) C1(24.716,3.175) C2(23.446,3.175) C3(22.176,3.175) C4(20.906,3.175) C5(19.636,3.175) C6(18.366,3.175) C7(17.096,3.175) C8(15.826,3.175) C9(14.556,3.175) C10(13.286,3.175) C11(12.016,3.175) C12(10.746,3.175) C13(9.476,3.175) C14(8.206,3.175) C15(6.936,3.175) C16(5.666,3.175) C17(4.396,3.175) C18(3.126,3.175) C19(1.856,3.175) C20(0.586,3.175) C21(-0.684,3.175) C22(-1.954,3.175) C23(-3.224,3.175) C24(-4.494,3.175) C25(-5.764,3.175) C26(-7.034,3.175) C27(-8.304,3.175) C28(-9.574,3.175) C29(-10.844,3.175) C30(-12.114,3.175) C31(-13.384,3.175) C32(-14.654,3.175) C33(-15.924,3.175) C34(-17.194,3.175) C35(-18.464,3.175) C36(-19.734,3.175) C37(-21.004,3.175) C38(-22.274,3.175) C39(-23.544,3.175) C40(-24.814,3.175) D1(24.716,1.905) D2(23.446,1.905) D3(22.176,1.905) D4(20.906,1.905) D5(19.636,1.905) D6(18.366,1.905) D7(17.096,1.905) D8(15.826,1.905) D9(14.556,1.905) D10(13.286,1.905) D11(12.016,1.905) D12(10.746,1.905) D13(9.476,1.905) D14(8.206,1.905) D15(6.936,1.905) D16(5.666,1.905) D17(4.396,1.905) D18(3.126,1.905) D19(1.856,1.905) D20(0.586,1.905) D21(-0.684,1.905) D22(-1.954,1.905) D23(-3.224,1.905) D24(-4.494,1.905) D25(-5.764,1.905) D26(-7.034,1.905) D27(-8.304,1.905) D28(-9.574,1.905) D29(-10.844,1.905) D30(-12.114,1.905) D31(-13.384,1.905) D32(-14.654,1.905) D33(-15.924,1.905) D34(-17.194,1.905) D35(-18.464,1.905) D36(-19.734,1.905) D37(-21.004,1.905) D38(-22.274,1.905) D39(-23.544,1.905) D40(-24.814,1.905) E1(24.716,0.635) E2(23.446,0.635) E3(22.176,0.635) E4(20.906,0.635) E5(19.636,0.635) E6(18.366,0.635) E7(17.096,0.635) E8(15.826,0.635) E9(14.556,0.635) E10(13.286,0.635) E11(12.016,0.635) E12(10.746,0.635) E13(9.476,0.635) E14(8.206,0.635) E15(6.936,0.635) E16(5.666,0.635) E17(4.396,0.635) E18(3.126,0.635) E19(1.856,0.635) E20(0.586,0.635) E21(-0.684,0.635) E22(-1.954,0.635) E23(-3.224,0.635) E24(-4.494,0.635) E25(-5.764,0.635) E26(-7.034,0.635) E27(-8.304,0.635) E28(-9.574,0.635) E29(-10.844,0.635) E30(-12.114,0.635) E31(-13.384,0.635) E32(-14.654,0.635) E33(-15.924,0.635) E34(-17.194,0.635) E35(-18.464,0.635) E36(-19.734,0.635) E37(-21.004,0.635) E38(-22.274,0.635) E39(-23.544,0.635) E40(-24.814,0.635) F1(24.716,-0.635) F2(23.446,-0.635) F3(22.176,-0.635) F4(20.906,-0.635) F5(19.636,-0.635) F6(18.366,-0.635) F7(17.096,-0.635) F8(15.826,-0.635) F9(14.556,-0.635) F10(13.286,-0.635) F11(12.016,-0.635) F12(10.746,-0.635) F13(9.476,-0.635) F14(8.206,-0.635) F15(6.936,-0.635) F16(5.666,-0.635) F17(4.396,-0.635) F18(3.126,-0.635) F19(1.856,-0.635) F20(0.586,-0.635) F21(-0.684,-0.635) F22(-1.954,-0.635) F23(-3.224,-0.635) F24(-4.494,-0.635) F25(-5.764,-0.635) F26(-7.034,-0.635) F27(-8.304,-0.635) F28(-9.574,-0.635) F29(-10.844,-0.635) F30(-12.114,-0.635) F31(-13.384,-0.635) F32(-14.654,-0.635) F33(-15.924,-0.635) F34(-17.194,-0.635) F35(-18.464,-0.635) F36(-19.734,-0.635) F37(-21.004,-0.635) F38(-22.274,-0.635) F39(-23.544,-0.635) F40(-24.814,-0.635) G1(24.716,-1.905) G2(23.446,-1.905) G3(22.176,-1.905) G4(20.906,-1.905) G5(19.636,-1.905) G6(18.366,-1.905) G7(17.096,-1.905) G8(15.826,-1.905) G9(14.556,-1.905) G10(13.286,-1.905) G11(12.016,-1.905) G12(10.746,-1.905) G13(9.476,-1.905) G14(8.206,-1.905) G15(6.936,-1.905) G16(5.666,-1.905) G17(4.396,-1.905) G18(3.126,-1.905) G19(1.856,-1.905) G20(0.586,-1.905) G21(-0.684,-1.905) G22(-1.954,-1.905) G23(-3.224,-1.905) G24(-4.494,-1.905) G25(-5.764,-1.905) G26(-7.034,-1.905) G27(-8.304,-1.905) G28(-9.574,-1.905) G29(-10.844,-1.905) G30(-12.114,-1.905) G31(-13.384,-1.905) G32(-14.654,-1.905) G33(-15.924,-1.905) G34(-17.194,-1.905) G35(-18.464,-1.905) G36(-19.734,-1.905) G37(-21.004,-1.905) G38(-22.274,-1.905) G39(-23.544,-1.905) G40(-24.814,-1.905) H1(24.716,-3.175) H2(23.446,-3.175) H3(22.176,-3.175) H4(20.906,-3.175) H5(19.636,-3.175) H6(18.366,-3.175) H7(17.096,-3.175) H8(15.826,-3.175) H9(14.556,-3.175) H10(13.286,-3.175) H11(12.016,-3.175) H12(10.746,-3.175) H13(9.476,-3.175) H14(8.206,-3.175) H15(6.936,-3.175) H16(5.666,-3.175) H17(4.396,-3.175) H18(3.126,-3.175) H19(1.856,-3.175) H20(0.586,-3.175) H21(-0.684,-3.175) H22(-1.954,-3.175) H23(-3.224,-3.175) H24(-4.494,-3.175) H25(-5.764,-3.175) H26(-7.034,-3.175) H27(-8.304,-3.175) H28(-9.574,-3.175) H29(-10.844,-3.175) H30(-12.114,-3.175) H31(-13.384,-3.175) H32(-14.654,-3.175) H33(-15.924,-3.175) H34(-17.194,-3.175) H35(-18.464,-3.175) H36(-19.734,-3.175) H37(-21.004,-3.175) H38(-22.274,-3.175) H39(-23.544,-3.175) H40(-24.814,-3.175) J1(24.716,-4.445) J2(23.446,-4.445) J3(22.176,-4.445) J4(20.906,-4.445) J5(19.636,-4.445) J6(18.366,-4.445) J7(17.096,-4.445) J8(15.826,-4.445) J9(14.556,-4.445) J10(13.286,-4.445) J11(12.016,-4.445) J12(10.746,-4.445) J13(9.476,-4.445) J14(8.206,-4.445) J15(6.936,-4.445) J16(5.666,-4.445) J17(4.396,-4.445) J18(3.126,-4.445) J19(1.856,-4.445) J20(0.586,-4.445) J21(-0.684,-4.445) J22(-1.954,-4.445) J23(-3.224,-4.445) J24(-4.494,-4.445) J25(-5.764,-4.445) J26(-7.034,-4.445) J27(-8.304,-4.445) J28(-9.574,-4.445) J29(-10.844,-4.445) J30(-12.114,-4.445) J31(-13.384,-4.445) J32(-14.654,-4.445) J33(-15.924,-4.445) J34(-17.194,-4.445) J35(-18.464,-4.445) J36(-19.734,-4.445) J37(-21.004,-4.445) J38(-22.274,-4.445) J39(-23.544,-4.445) J40(-24.814,-4.445) K1(24.716,-5.715) K2(23.446,-5.715) K3(22.176,-5.715) K4(20.906,-5.715) K5(19.636,-5.715) K6(18.366,-5.715) K7(17.096,-5.715) K8(15.826,-5.715) K9(14.556,-5.715) K10(13.286,-5.715) K11(12.016,-5.715) K12(10.746,-5.715) K13(9.476,-5.715) K14(8.206,-5.715) K15(6.936,-5.715) K16(5.666,-5.715) K17(4.396,-5.715) K18(3.126,-5.715) K19(1.856,-5.715) K20(0.586,-5.715) K21(-0.684,-5.715) K22(-1.954,-5.715) K23(-3.224,-5.715) K24(-4.494,-5.715) K25(-5.764,-5.715) K26(-7.034,-5.715) K27(-8.304,-5.715) K28(-9.574,-5.715) K29(-10.844,-5.715) K30(-12.114,-5.715) K31(-13.384,-5.715) K32(-14.654,-5.715) K33(-15.924,-5.715) K34(-17.194,-5.715) K35(-18.464,-5.715) K36(-19.734,-5.715) K37(-21.004,-5.715) K38(-22.274,-5.715) K39(-23.544,-5.715) K40(-24.814,-5.715)
  silkscreen extent -28.49,-8.18 29.69,8.18, body extent -27.89,-7.34 29.49,7.34, height 7.07
CONN_USB-MINI-AB-651-305-142-821 [mm] "WE-USB2-MINI-AB TYPE"
  rect 0.5x2.3 smd: 1(-1.6,2.8) 2(-0.8,2.8) 3(0,2.8) 4(0.8,2.8) 5(1.6,2.8)
  rect 2x2.5 smd: 6(4.45,2.7) 7(4.45,-2.8) 8(-4.45,-2.8) 9(-4.45,2.7)
  silkscreen extent -4.03,-5.6 4,1.1, body extent -4.95,-5.72 4.95,3.68, height 4.12
DBV0005A_N [mm] "SOT23, 5-Leads, Body 2.9x1.6mm, Pitch 0.95mm, Lead Span 2.8mm, IPC Medium Density"
  rect 1.1x0.65 smd: 1(-1.2,0.95) 2(-1.2,0) 3(-1.2,-0.95) 4(1.2,-0.95) 5(1.2,0.95)
  silkscreen extent -1.33,-1.55 0.25,1.95, body extent -0.87,-1.52 0.87,1.53, height 1.45
DDA0008B_L [mm] "SOIC, 8-Leads, Body 4.9x3.9mm, Pitch 1.27mm, Exposed Pad, IPC High Density"
  oval 1.7x0.6 smd: 1(-2.45,1.905) 2(-2.45,0.635) 3(-2.45,-0.635) 4(-2.45,-1.905) 5(2.45,-1.905) 6(2.45,-0.635) 7(2.45,0.635) 8(2.45,1.905)
  rect 2.41x3.1 smd: 9(0,0)
  silkscreen extent -2.57,-2.5 1.2,2.88, body extent -2,-2.5 2,2.5, height 1.68
ESD_Overlay_Small [mil]
  silkscreen extent -62,-48 64,61
Fiducial10-30 [mm]
  round 1 smd paste-0.5 mask+1: 1(0,0)
  Keep-Out Layer circle w1.678: c0,0 r0.75
IND_TDK_ACM7060 [mm] "TDK Common Mode EMI Filter 7mmx6mm"
  rect 2.5x1.5 smd: 1(-3.25,1.5) 2(-3.25,-1.5) 3(3.25,-1.5) 4(3.25,1.5)
  silkscreen extent -4.8,-3.32 4.75,3.31, body extent -3.6,-3.12 3.6,3.07, height 3.55
Johnson_142-0701-80x [mil] "Johnson Components recommended land pattern"
  rect 25x200 smd: 1(0,0)
  rect 95x200 smd: 2(-172.5,0) 3(172.5,0)
  rect 95x200 smd far side: 4(-172.5,0) 5(172.5,0)
  silkscreen extent -235,-170 235,100, body extent -190,-92 190,480, height 165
